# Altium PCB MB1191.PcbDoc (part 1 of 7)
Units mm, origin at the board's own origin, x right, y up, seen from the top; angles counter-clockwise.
Board outline 130 x 80 mm, 8 copper layers (Top, F2, F3, F4, F5, F6, F7, Bottom), stack 1.115 mm thick; 358 components, 347 nets, 1452 pads, 1074 vias.
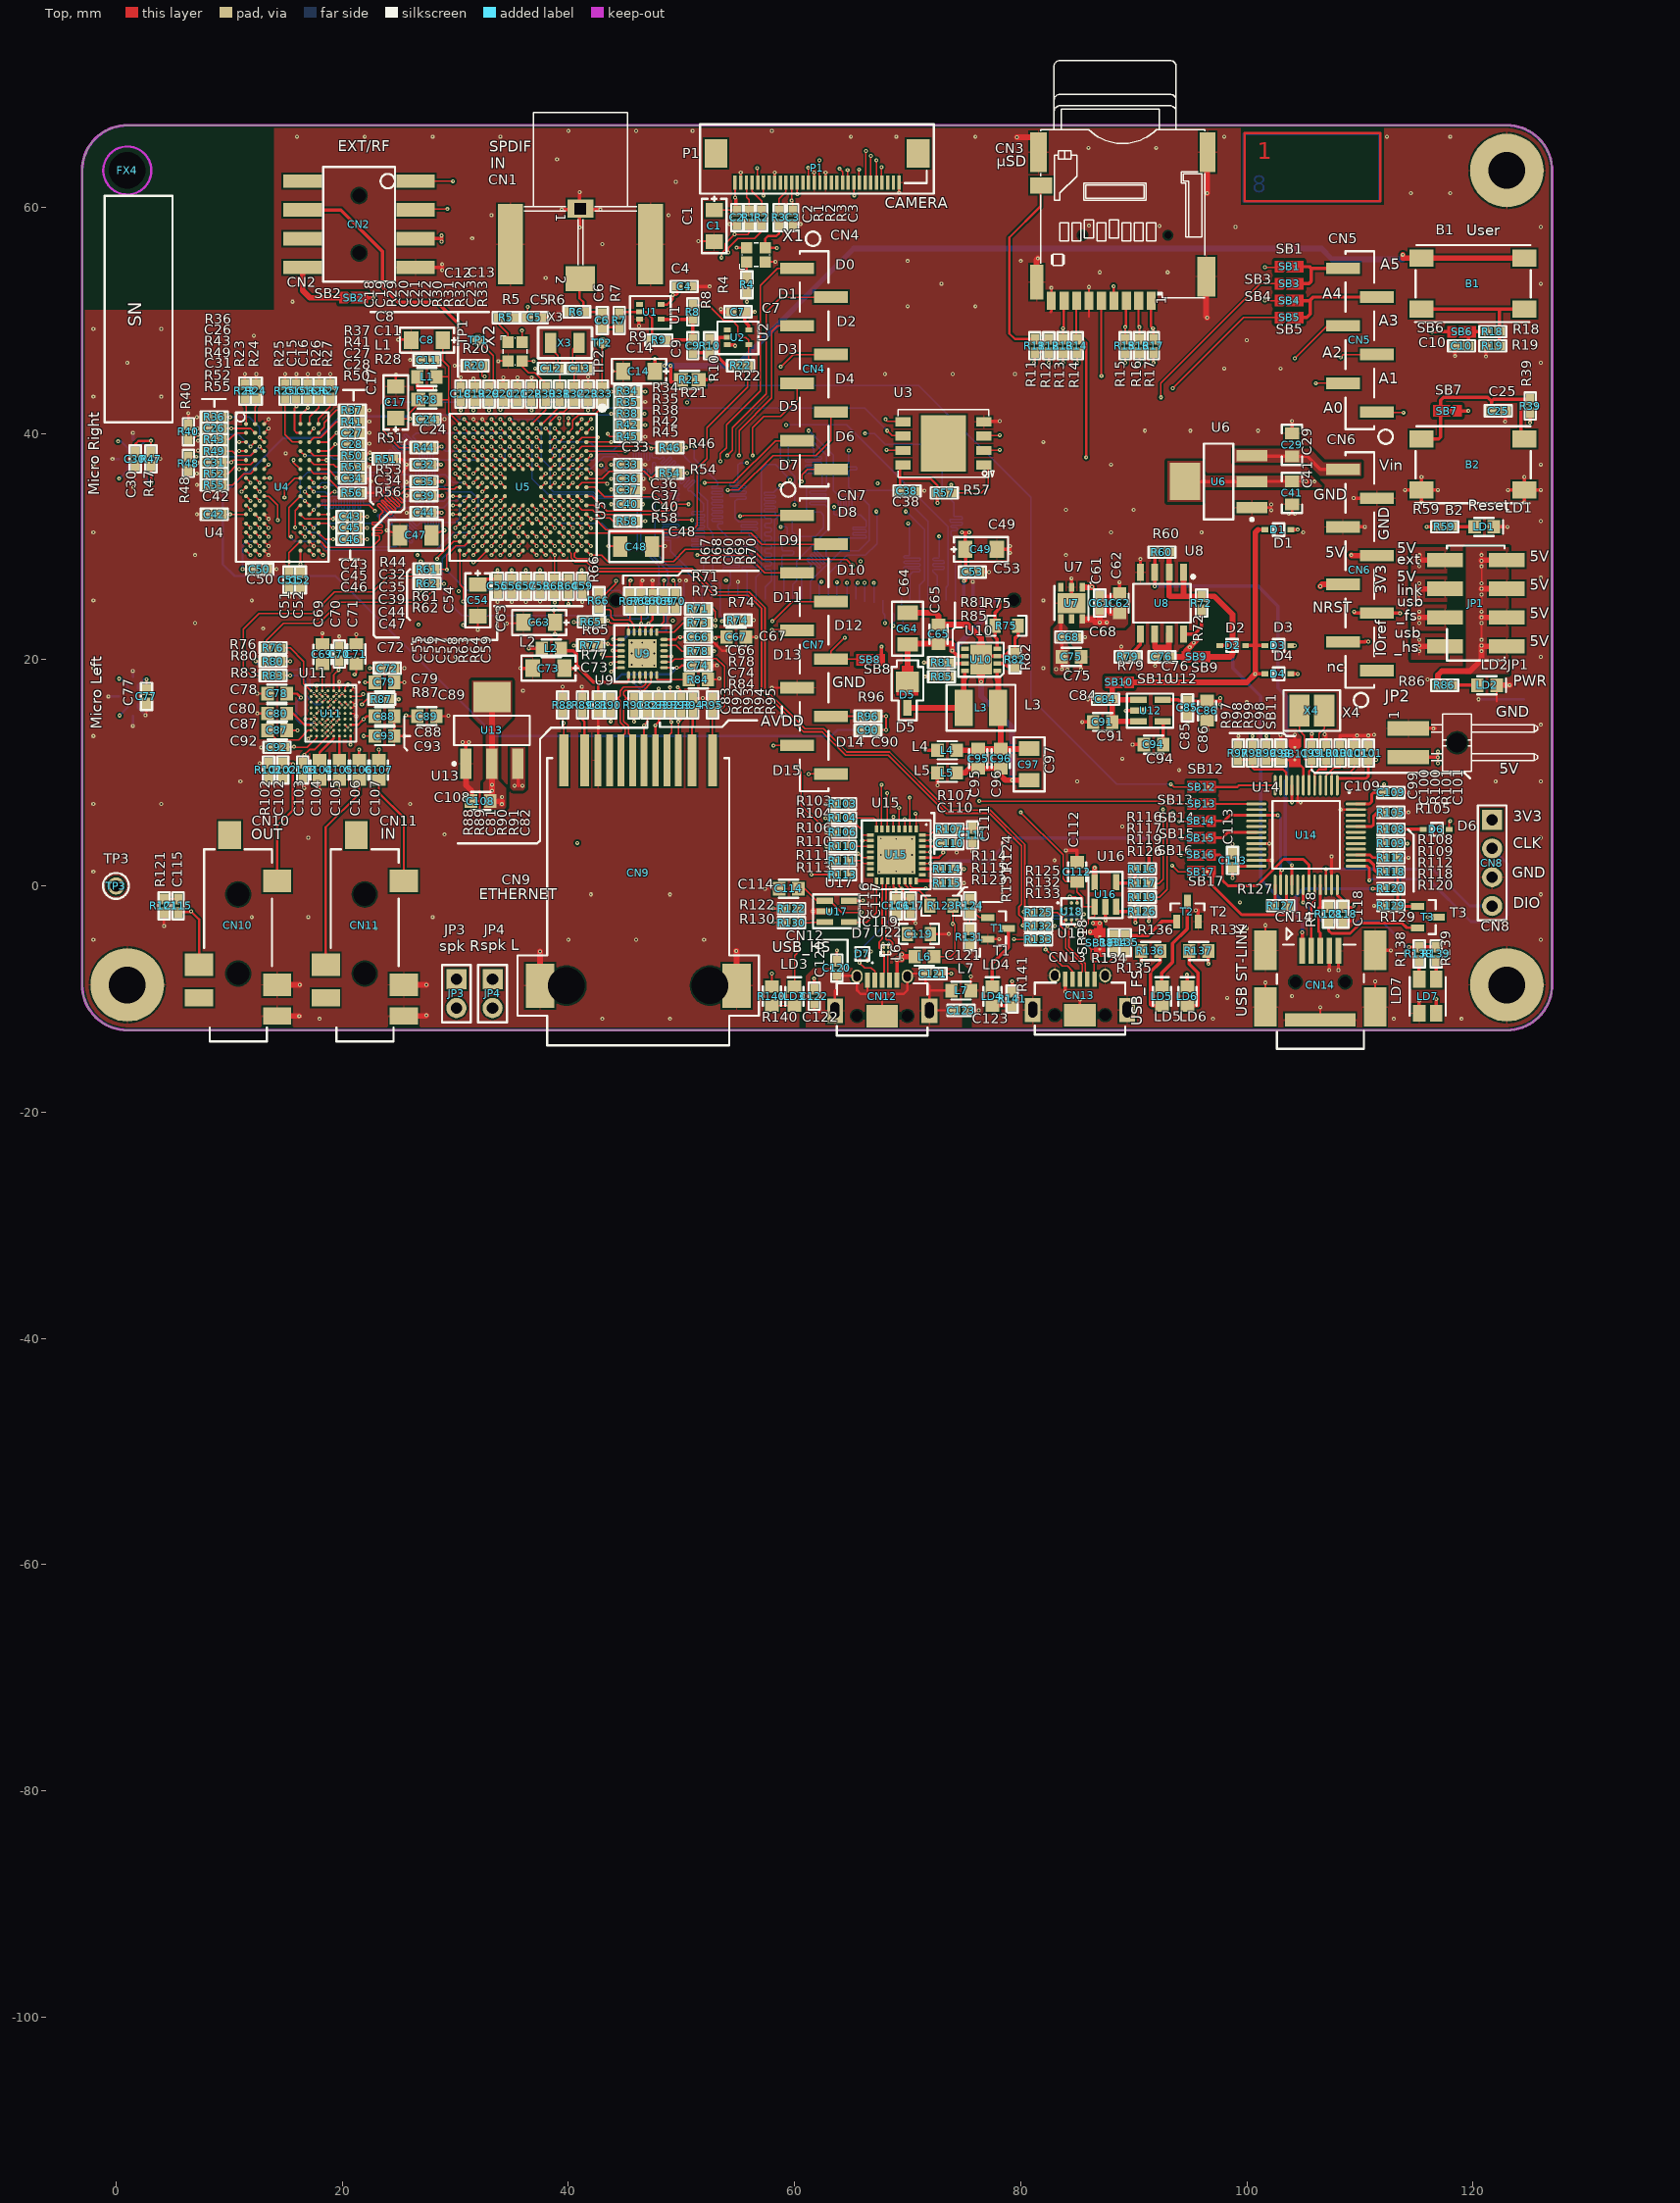
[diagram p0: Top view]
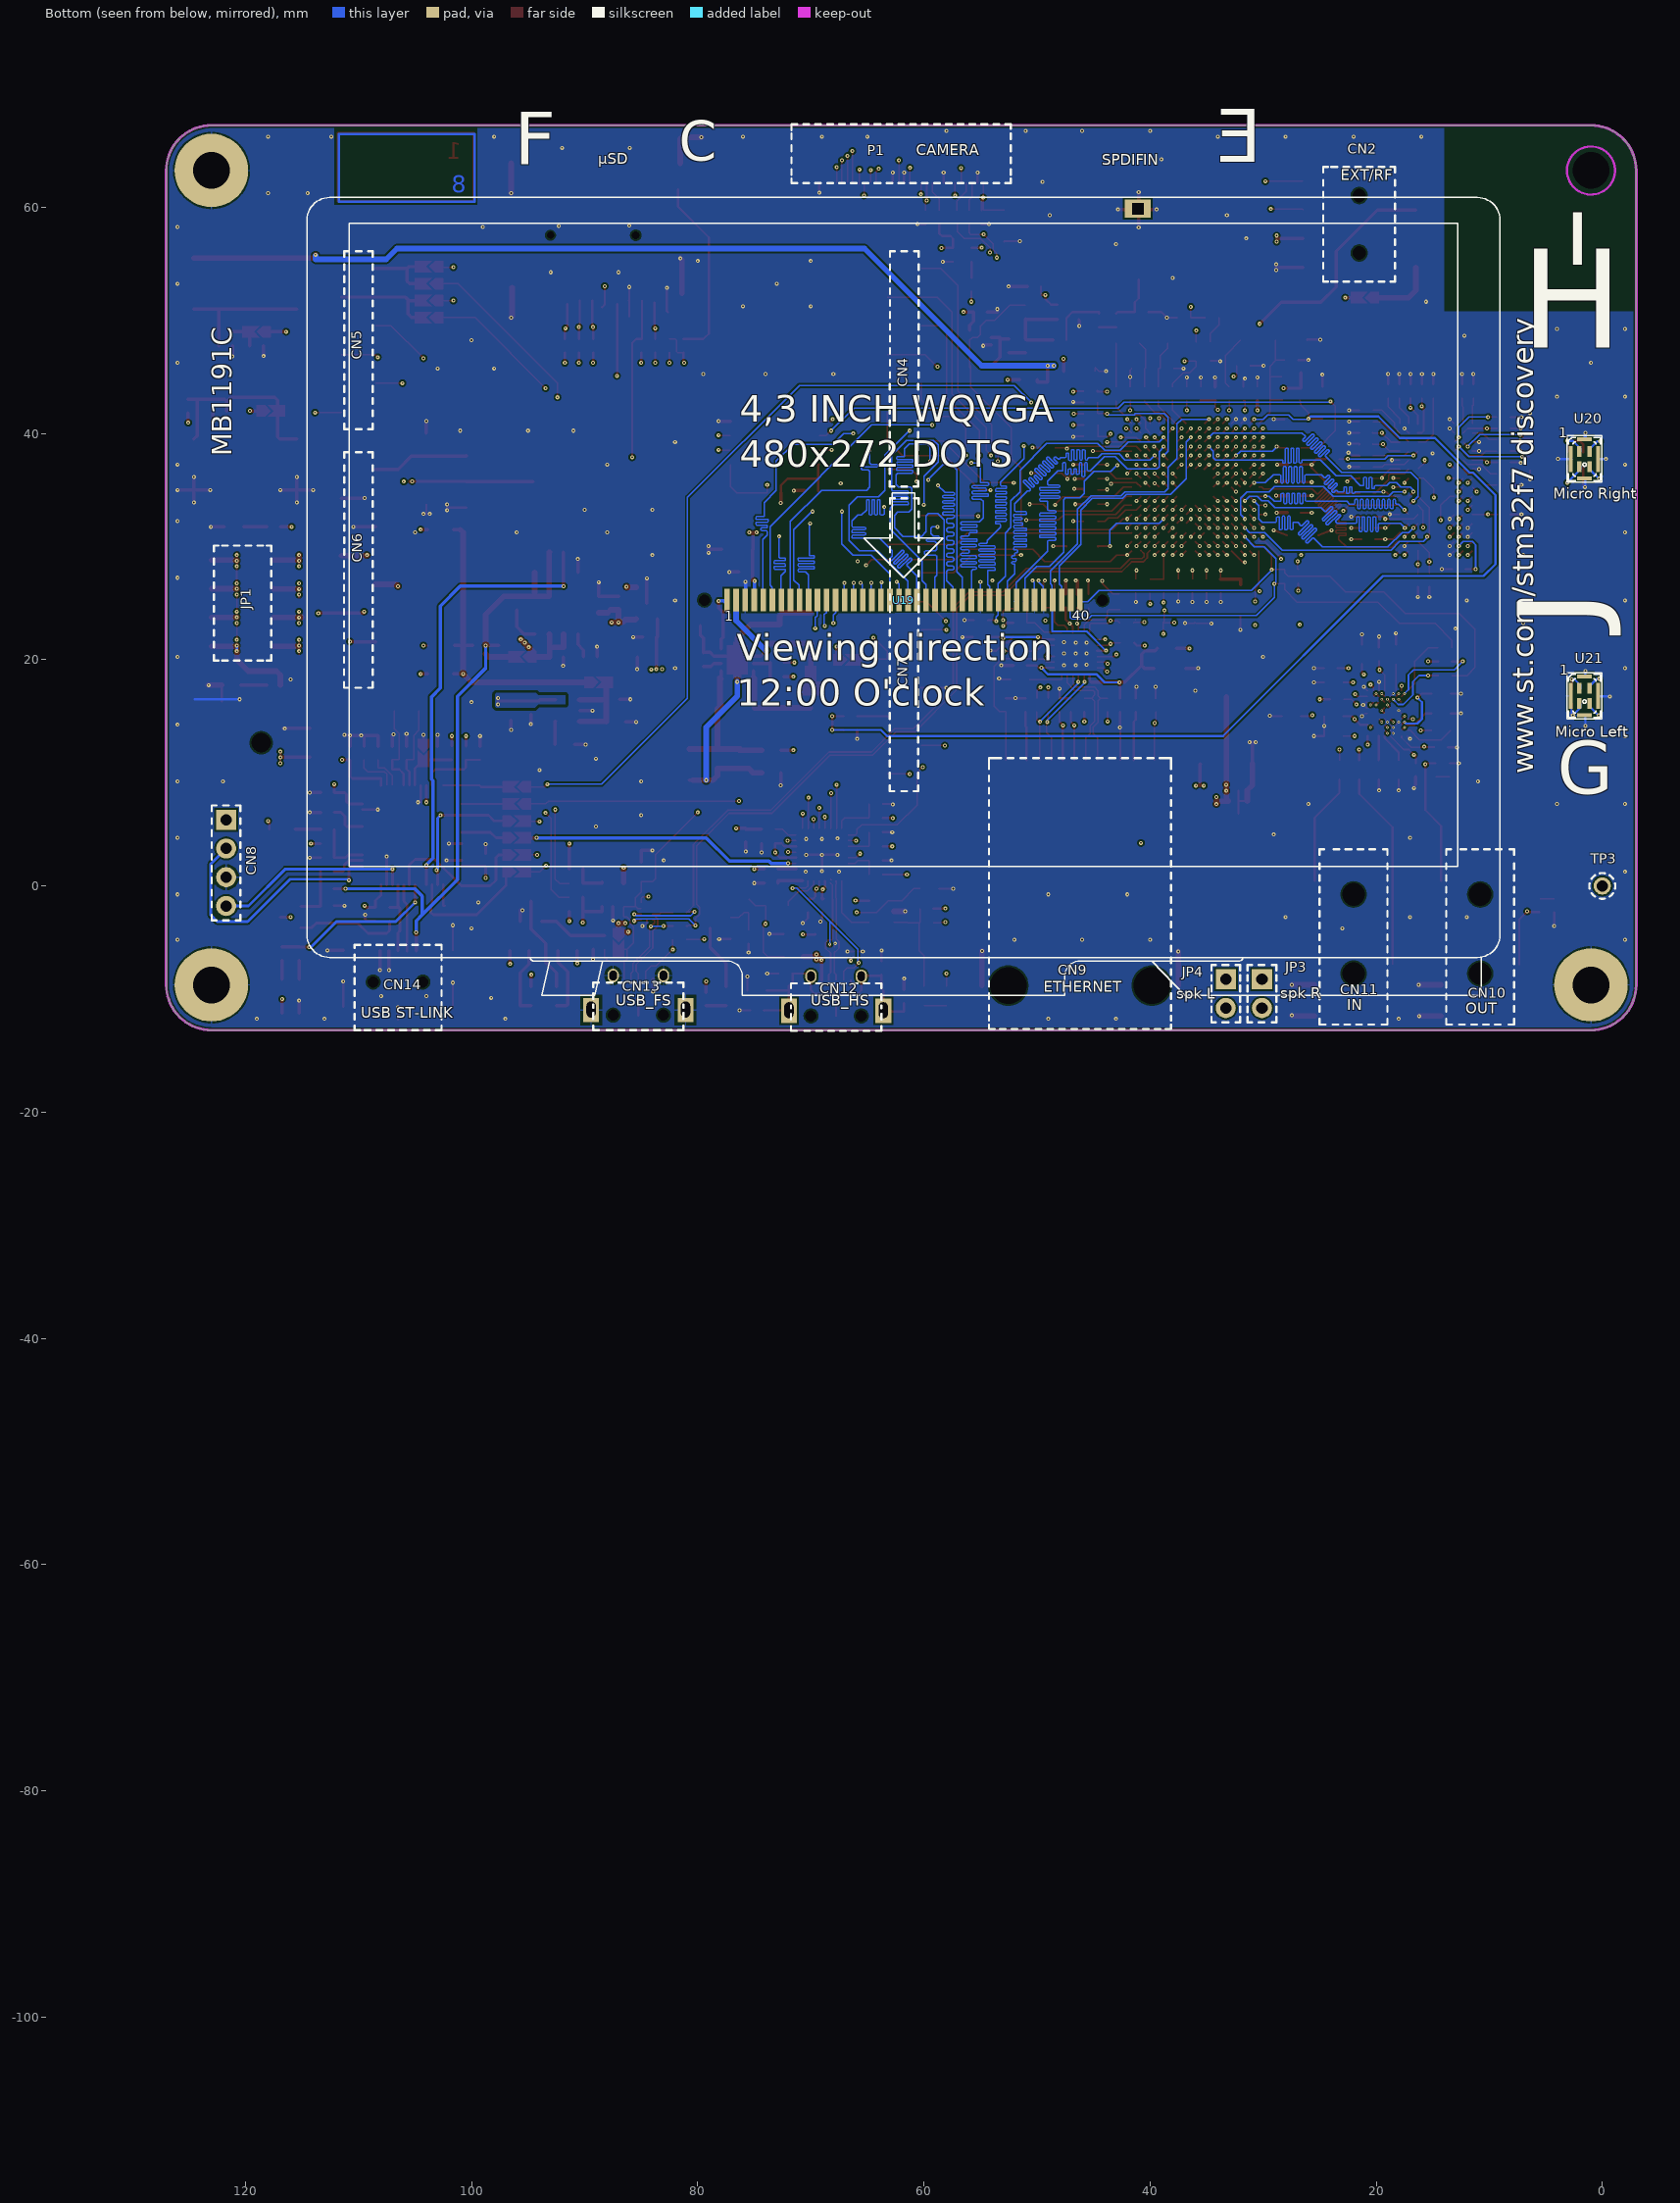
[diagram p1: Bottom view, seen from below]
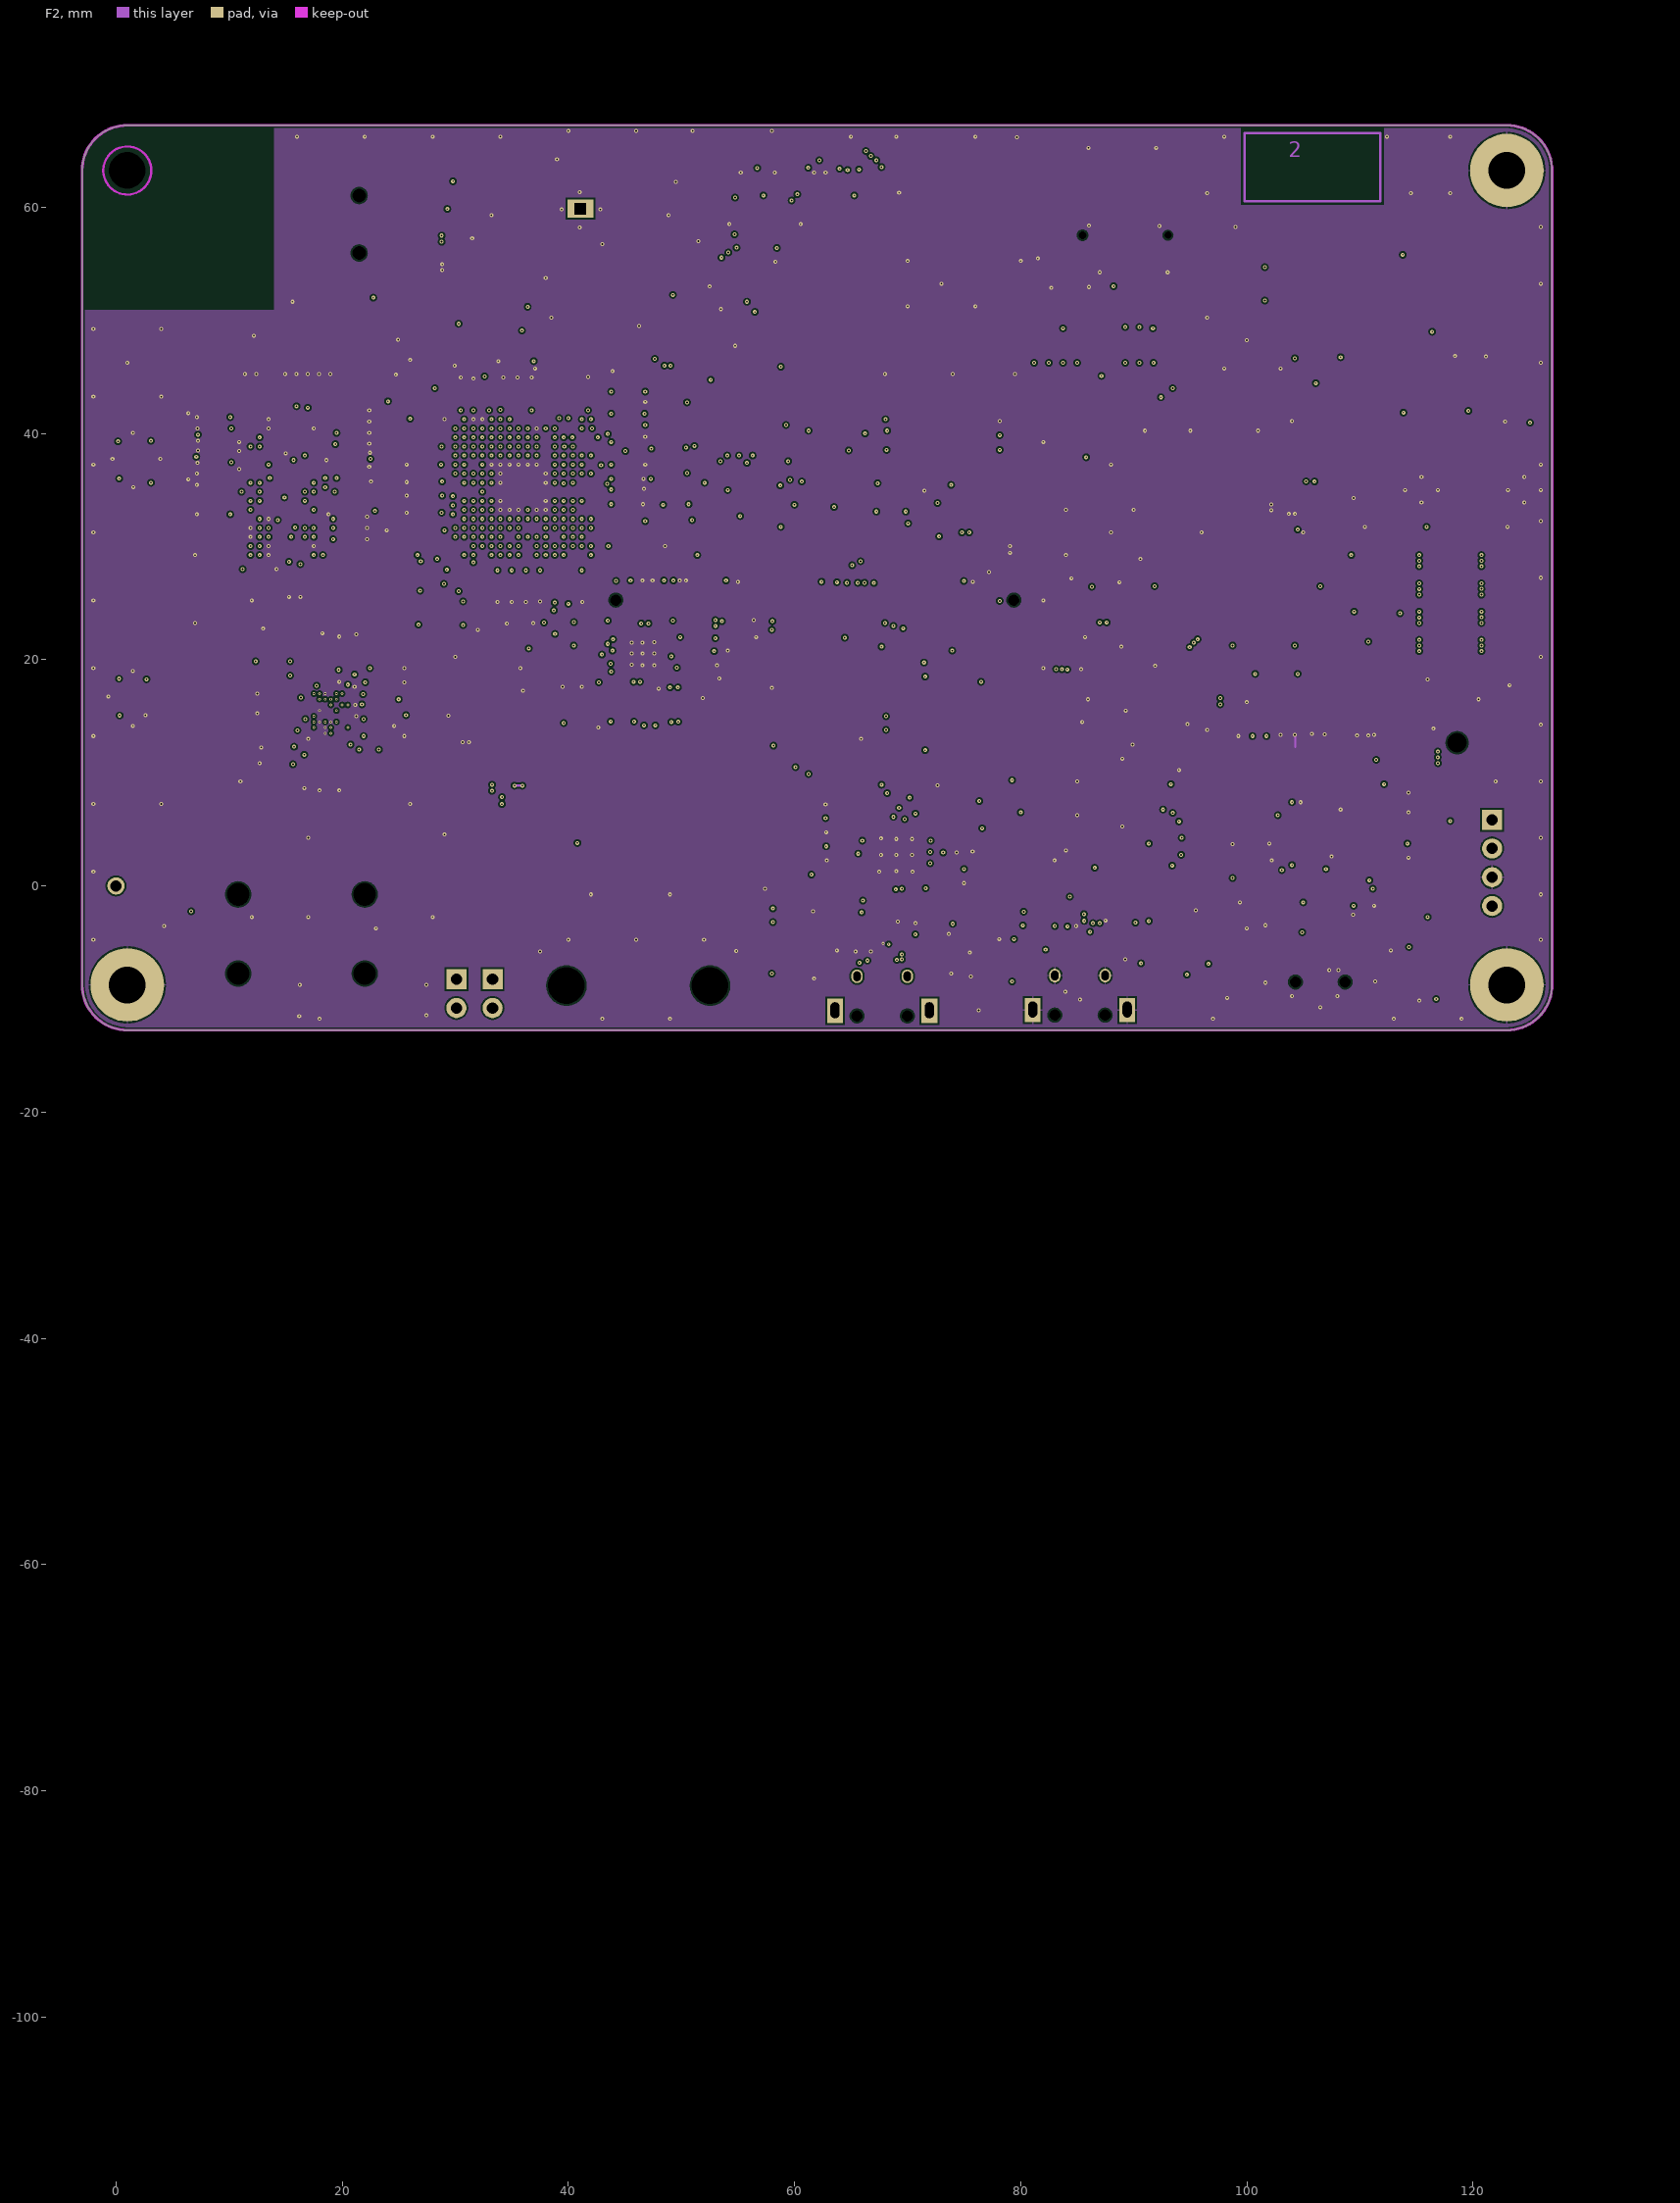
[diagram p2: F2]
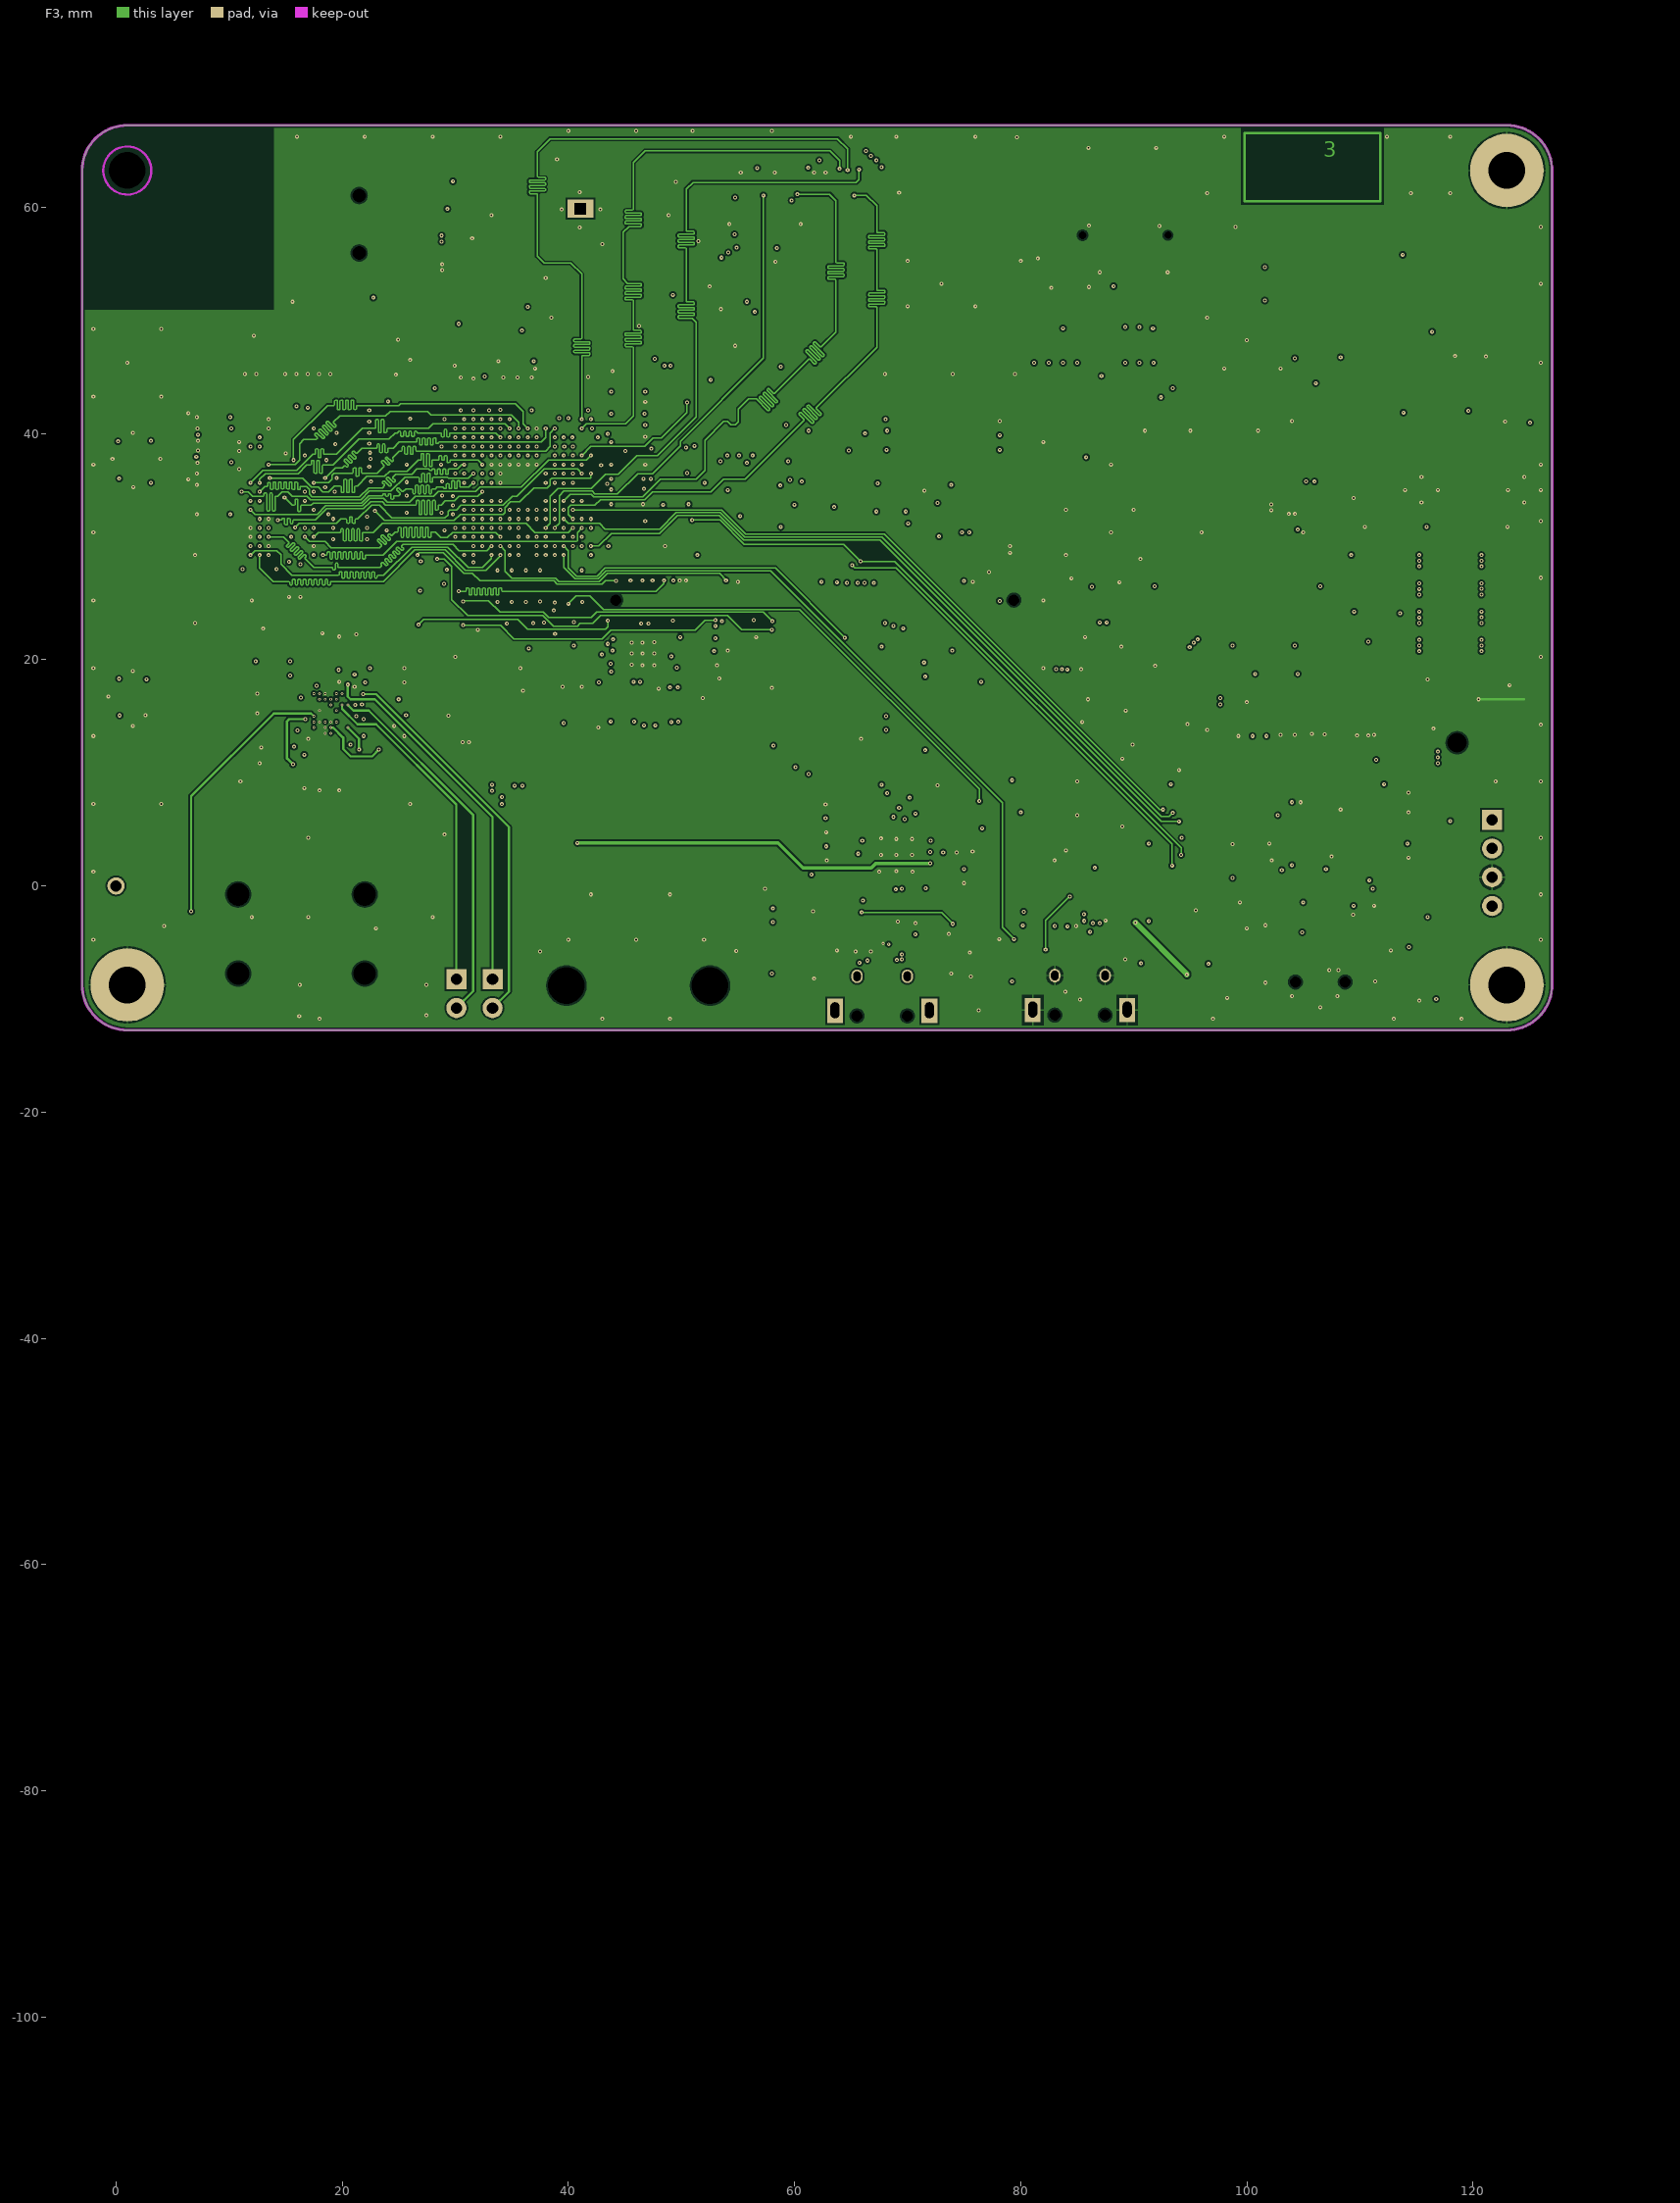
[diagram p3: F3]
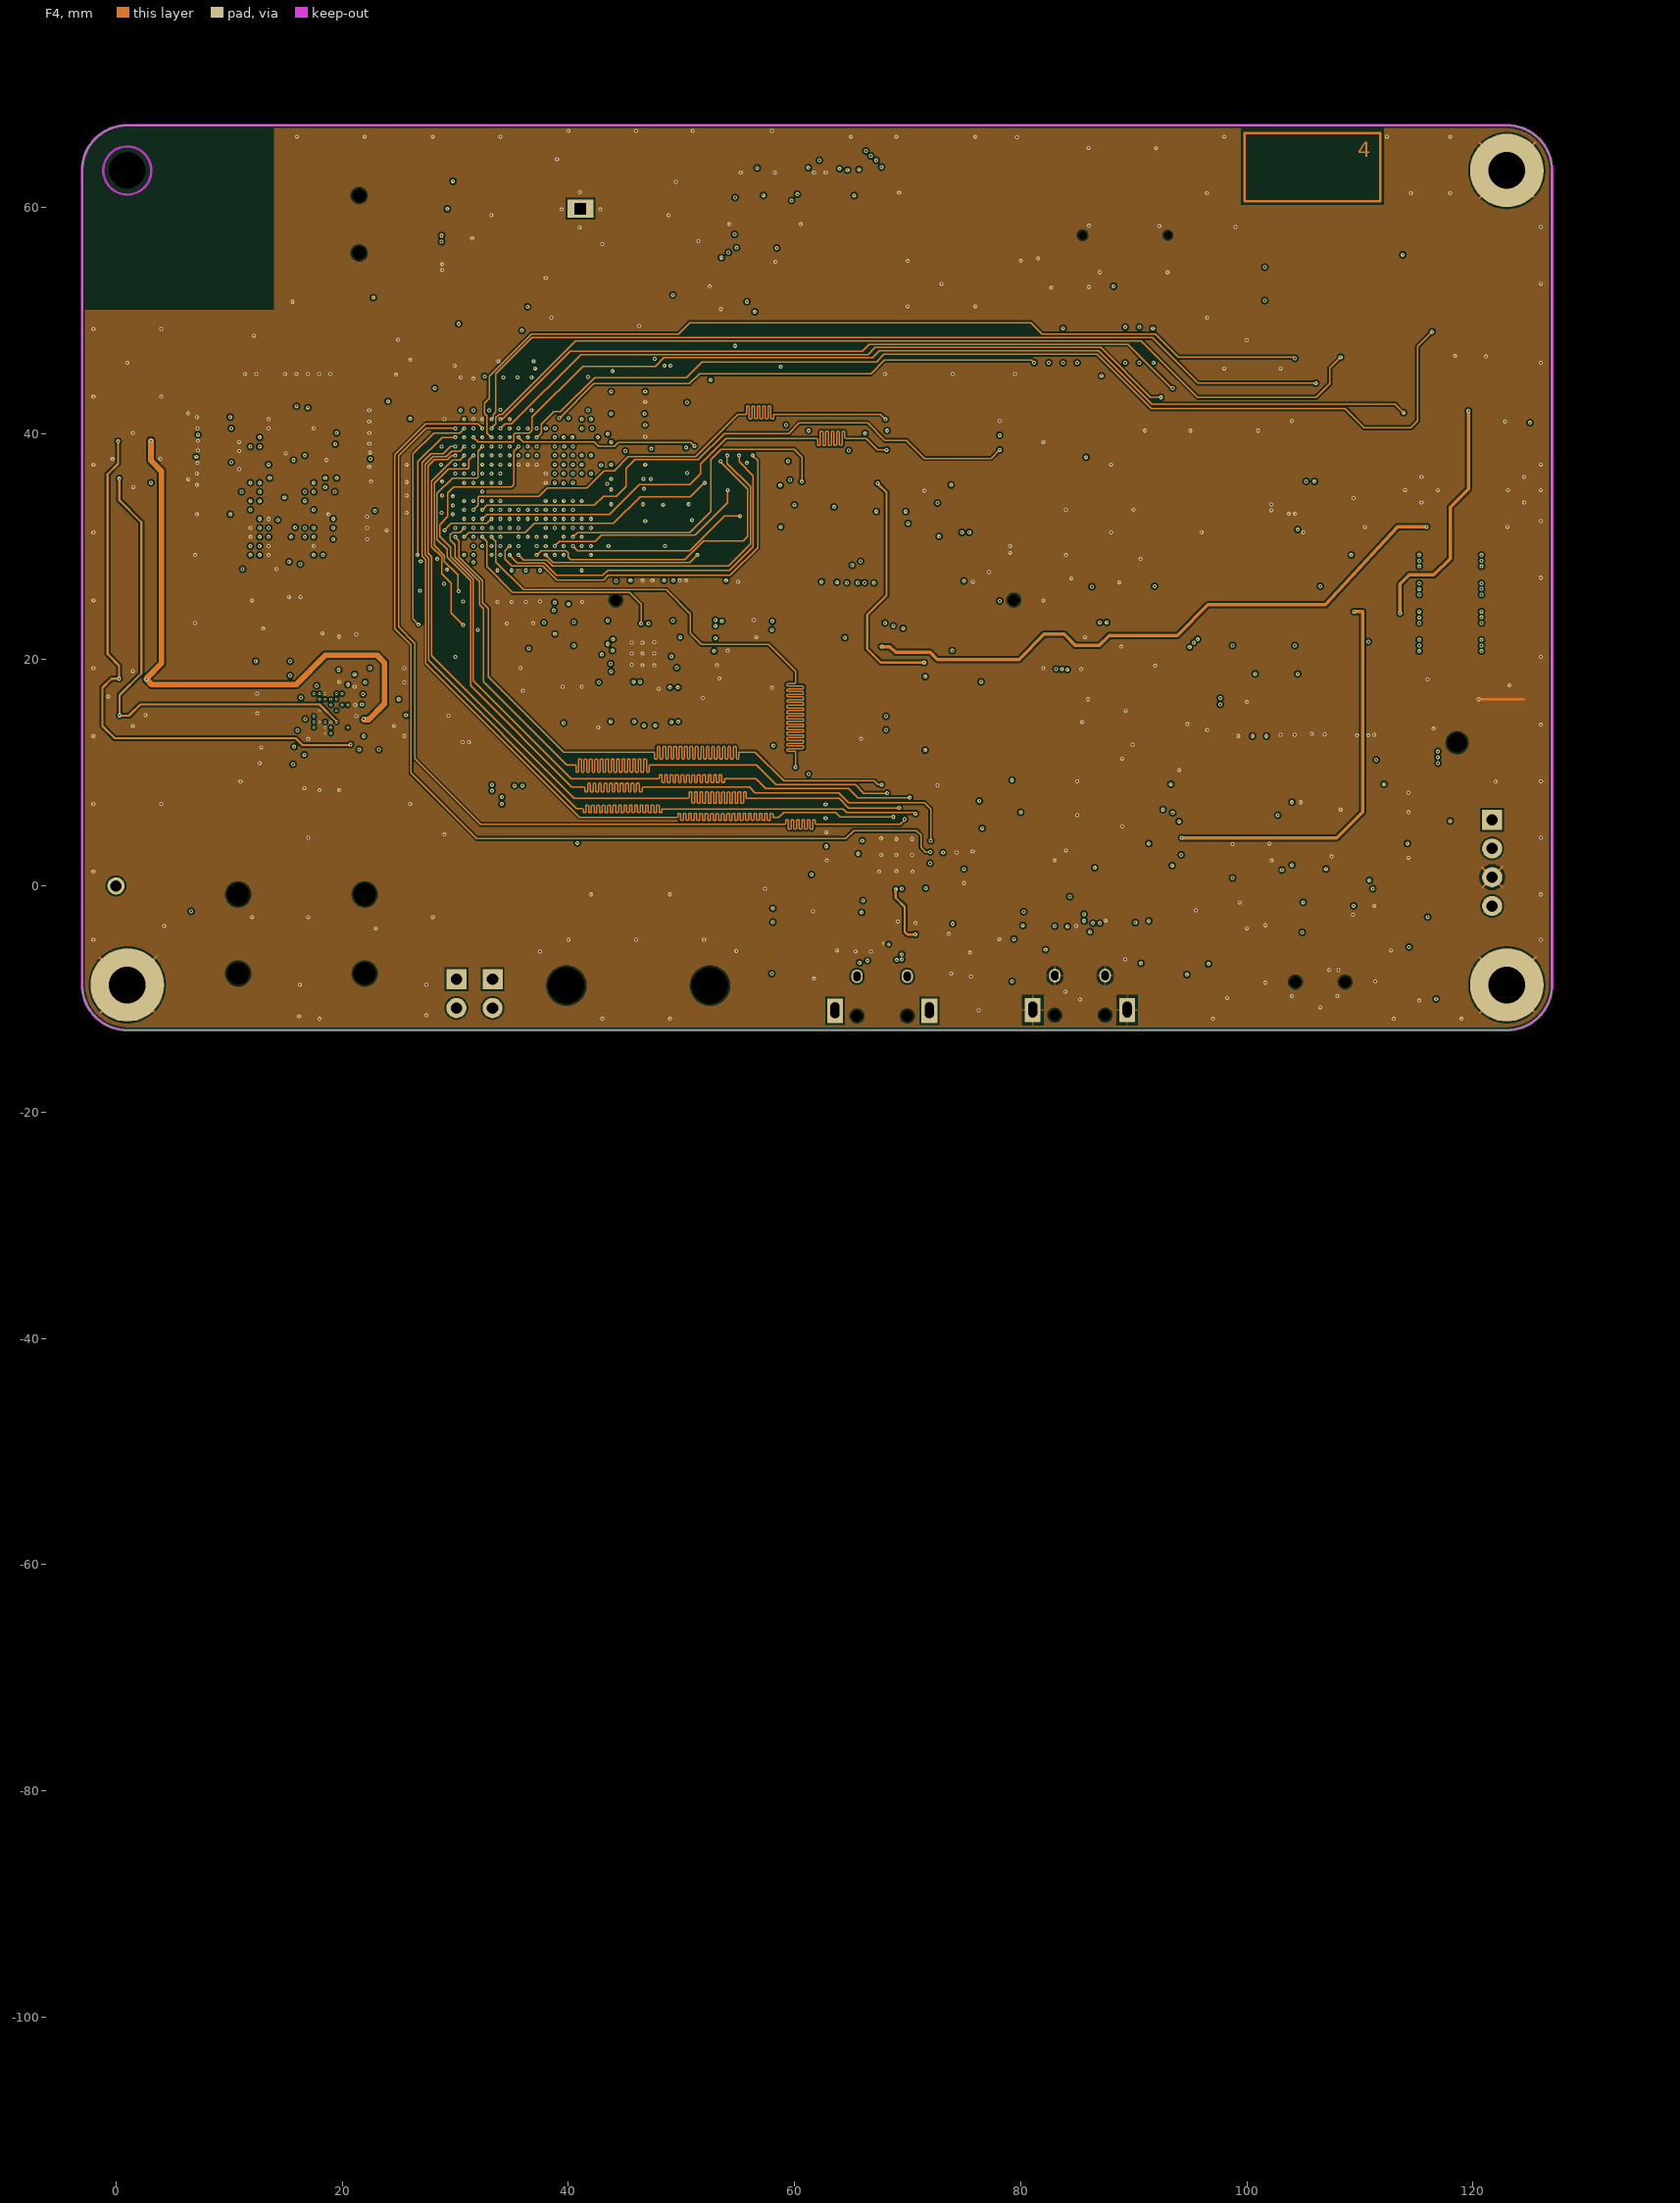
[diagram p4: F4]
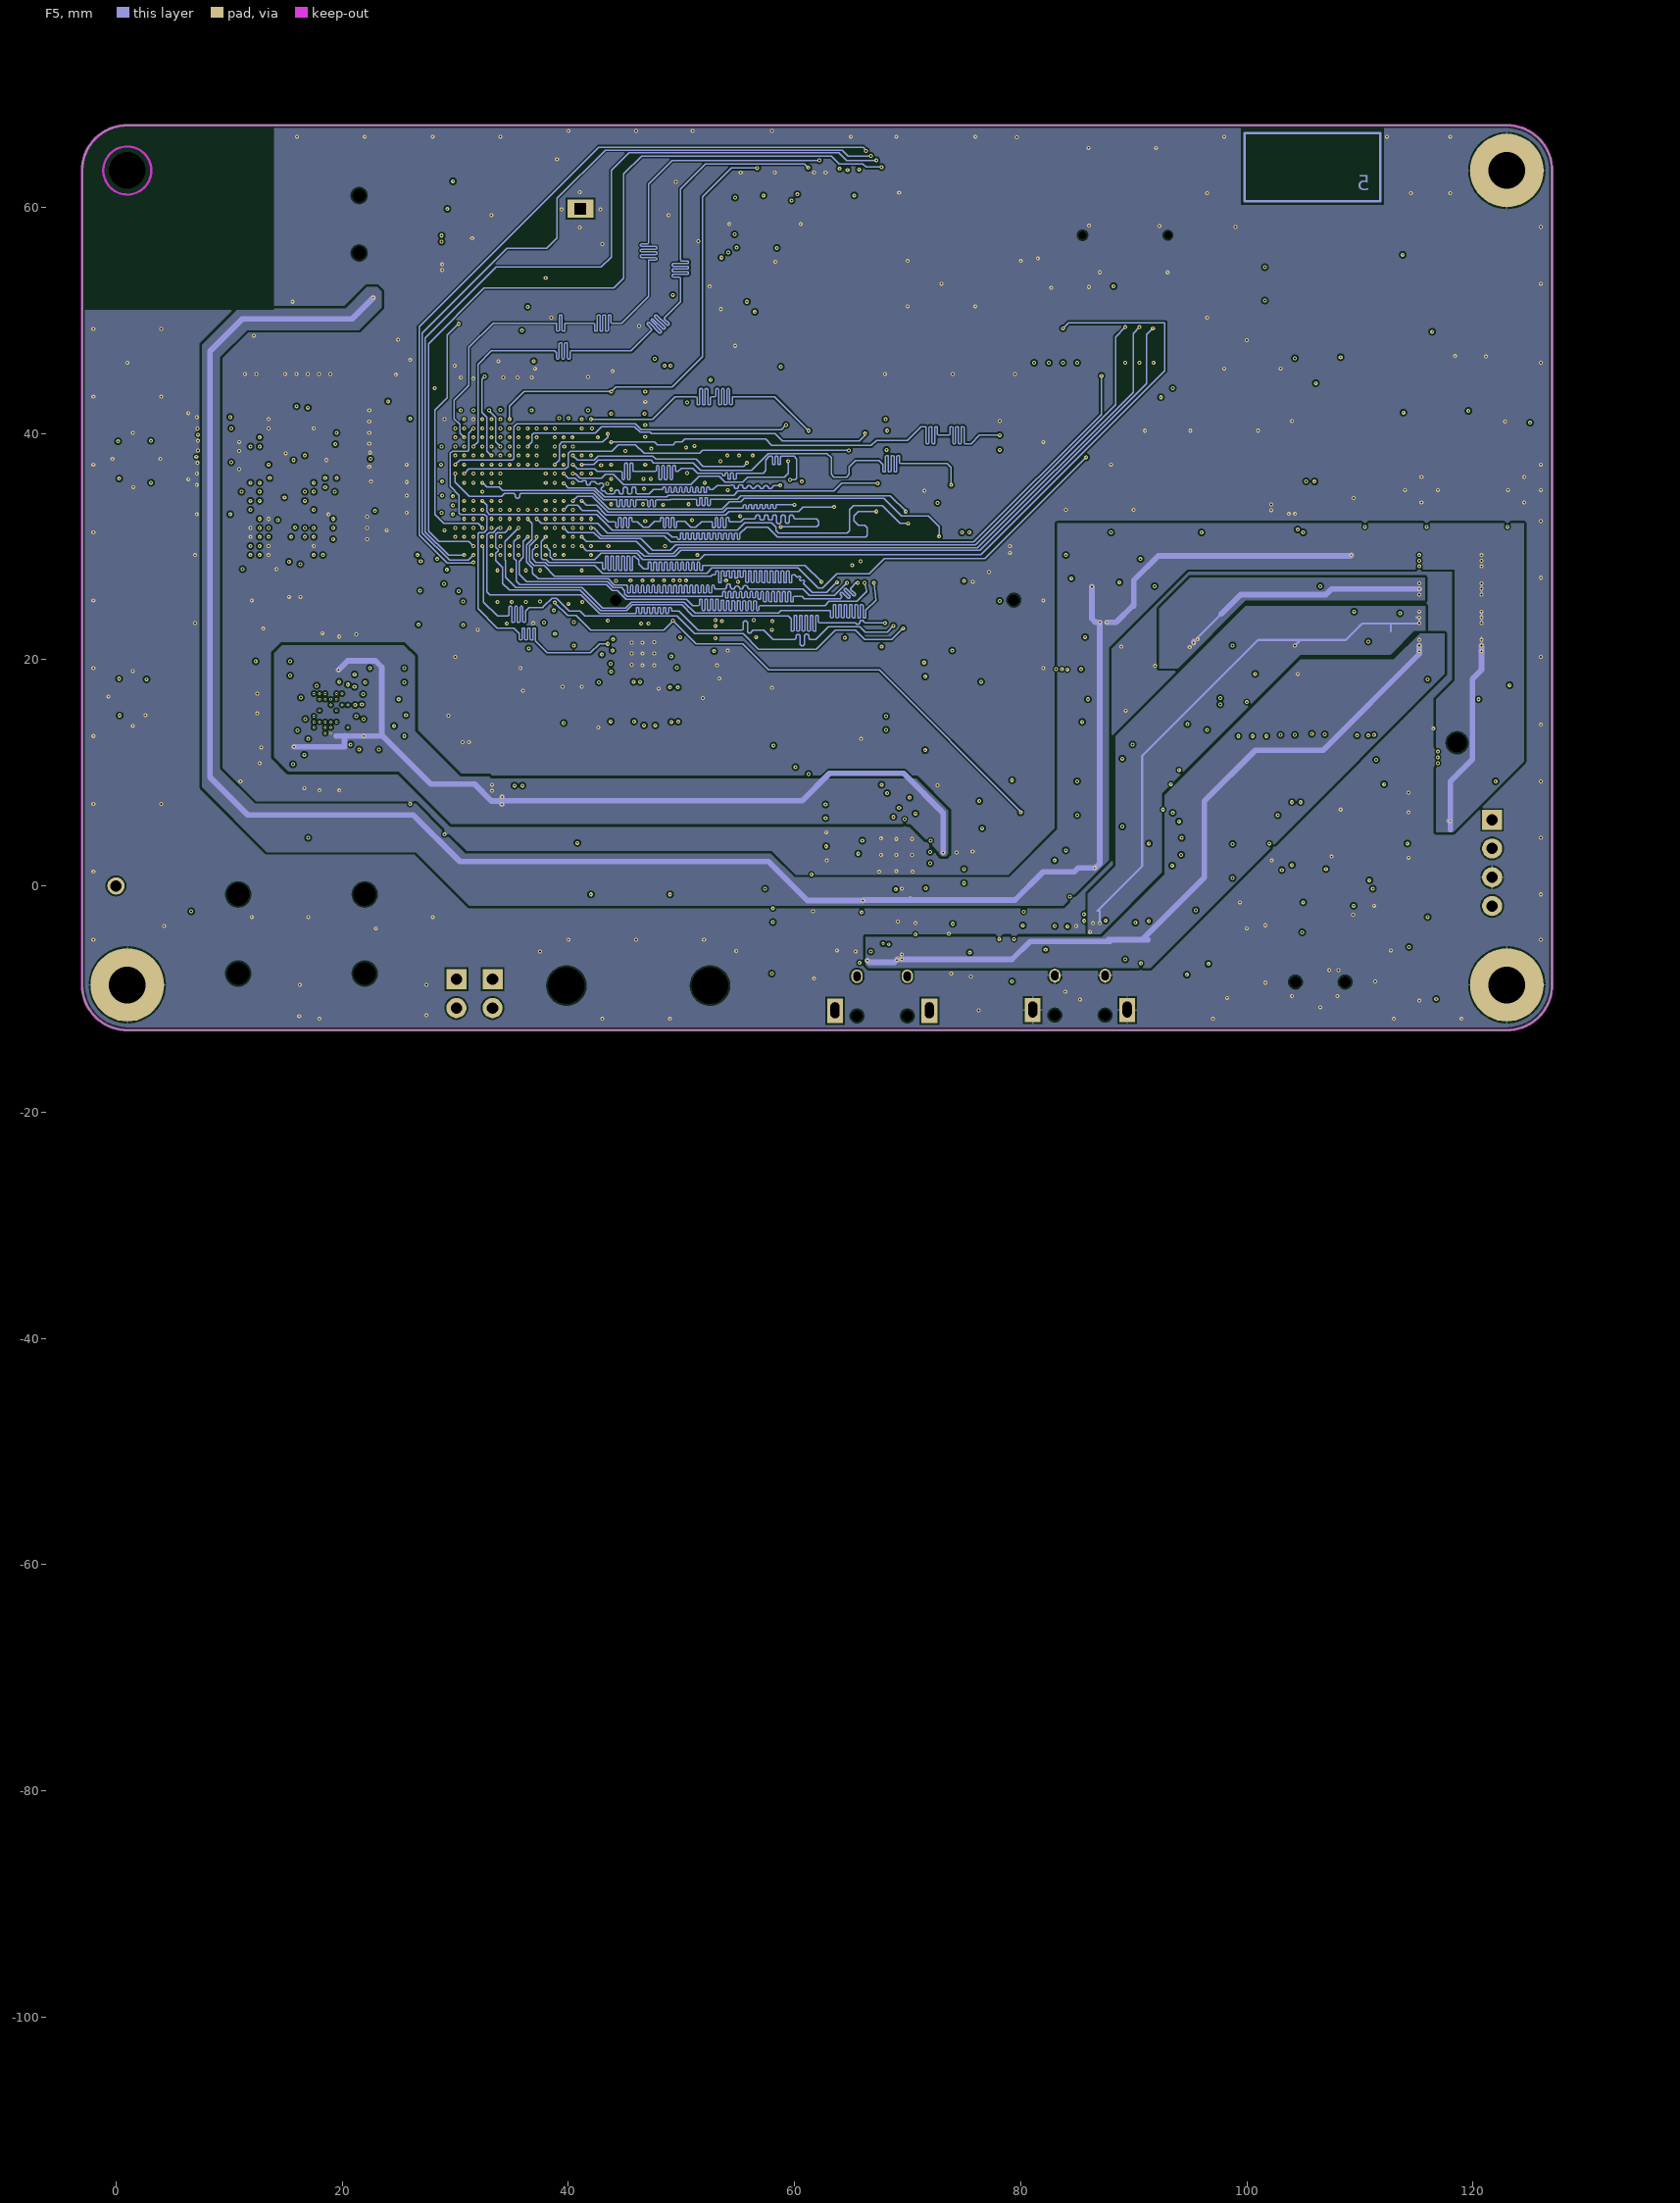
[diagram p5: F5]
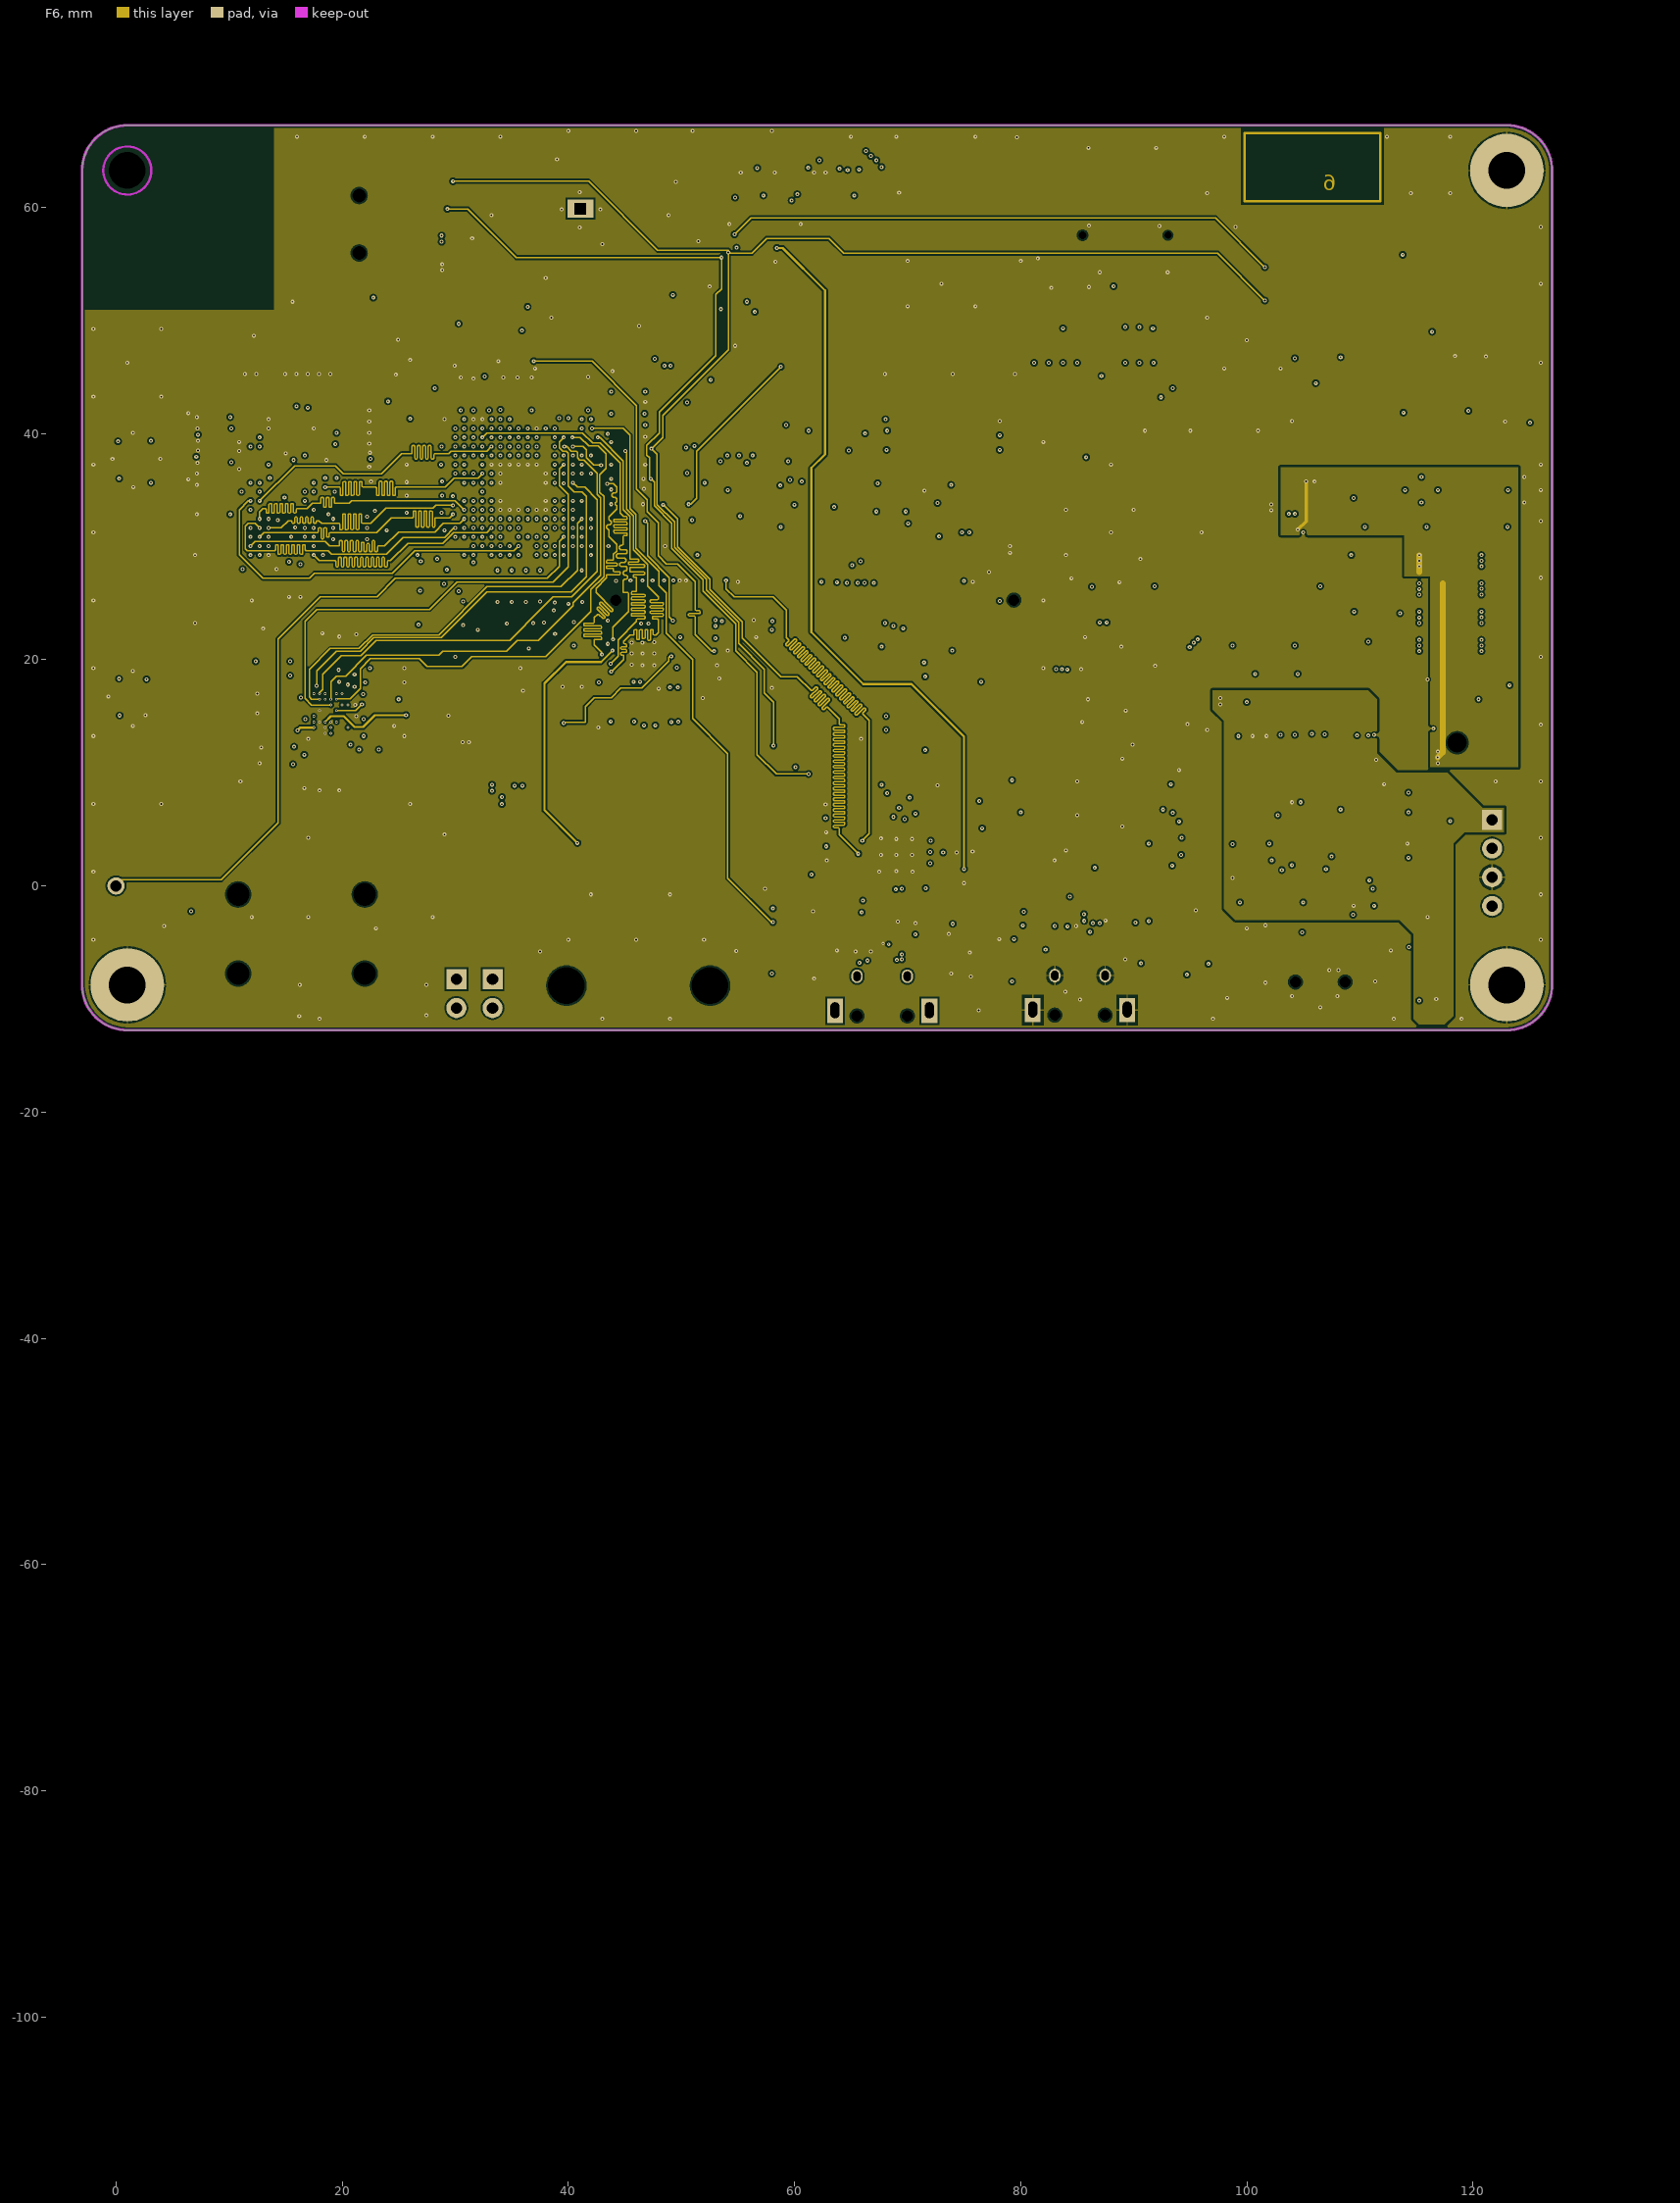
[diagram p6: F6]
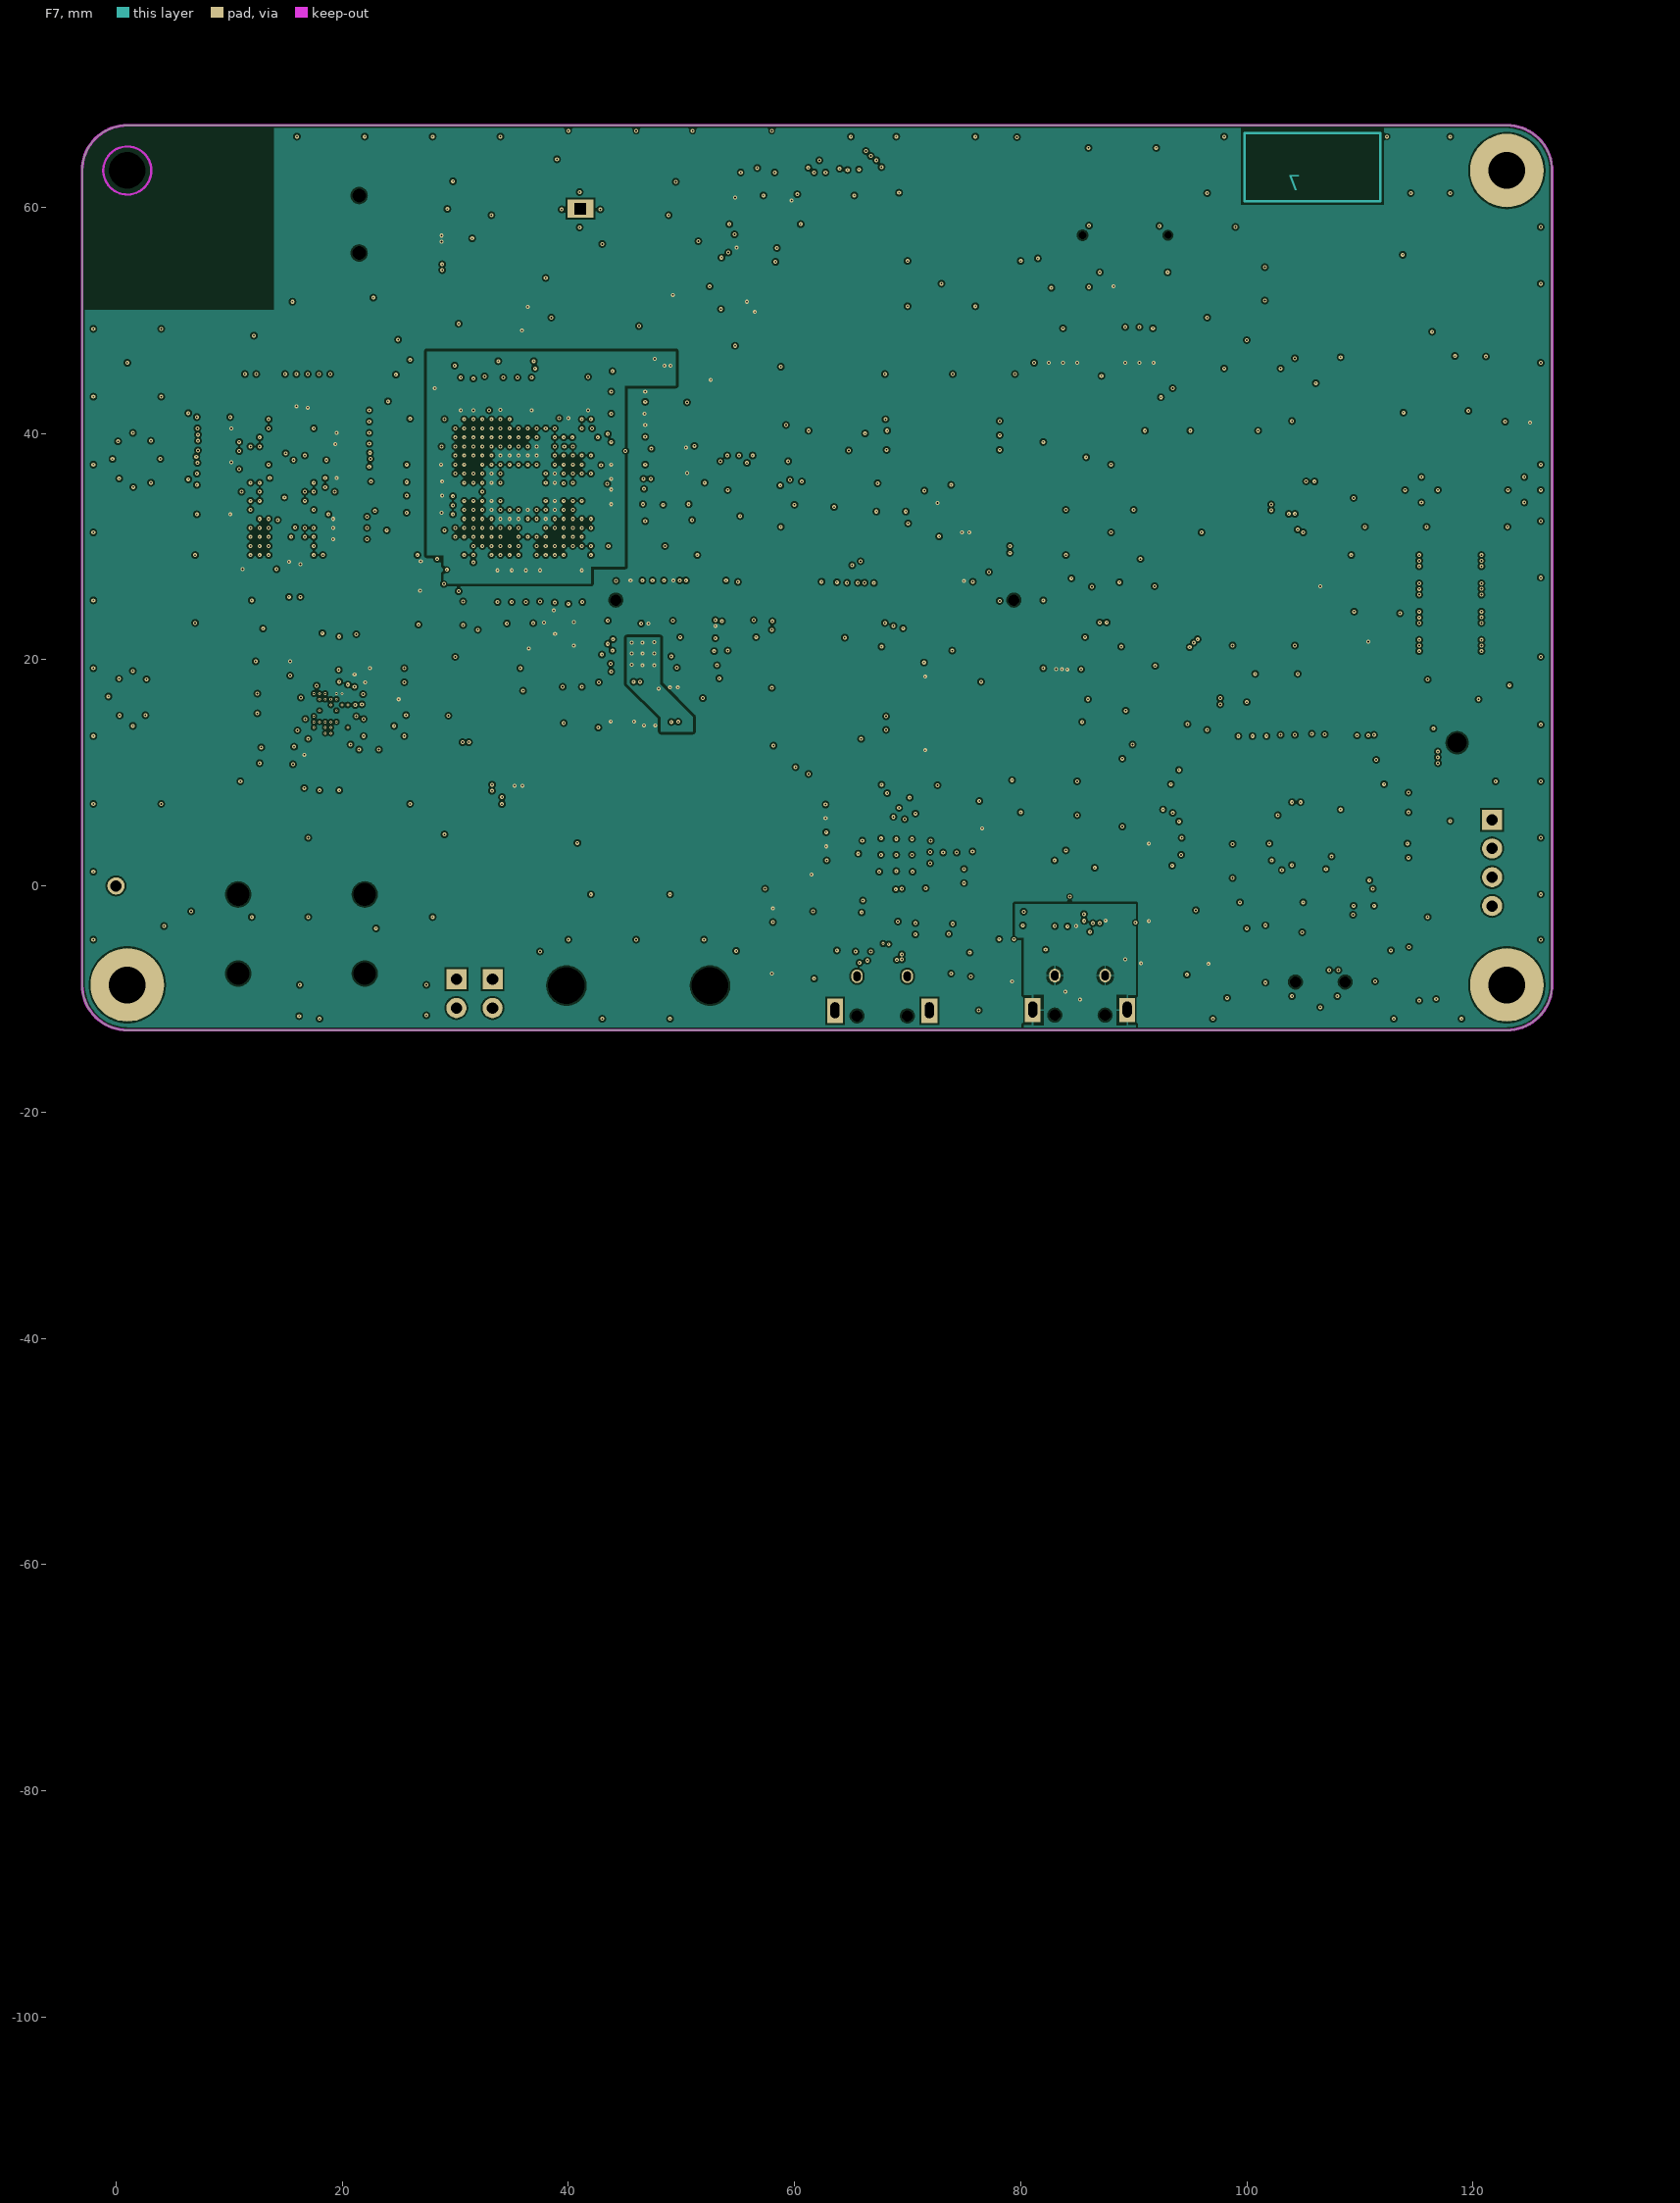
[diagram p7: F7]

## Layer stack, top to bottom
Top Mask: solder mask 0.015, Solder Resist, Dk 3.5
Top: signal copper 0.055
Dielectric 1: prepreg 0.108, Prepreg 2116, Dk 4.2
F2: signal copper 0.033
Dielectric2: core 0.125, Core 125, Dk 4.2
F3: signal copper 0.033
Dielectric3: prepreg 0.108, Prepreg 2116, Dk 4.2
F4: signal copper 0.033
Dielectric4: core 0.125, Core 125, Dk 4.2
F5: signal copper 0.033
Dielectric5: prepreg 0.108, Prepreg 2116, Dk 4.2
F6: signal copper 0.033
Dielectric6: core 0.125, Core 125, Dk 4.2
F7: signal copper 0.033
Dielectric7: prepreg 0.108, Prepreg 2116, Dk 4.2
Bottom: signal copper 0.055
Bottom Solder: solder mask 0.015, Solder Resist, Dk 3.5

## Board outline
-3,-8.75 ccw(c1,-8.75) 1,-12.75 123,-12.75 ccw(c123,-8.75) 127,-8.75 127,63.25 ccw(c123,63.25) 123,67.25 1,67.25 ccw(c1,63.25) -3,63.25

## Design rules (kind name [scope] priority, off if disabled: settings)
Clearance Clearance_CN1-1 [IsPad and (PadViaLibraryTemplate = 'r260_200hn100_160z0x0') vs InPolygon] p1: gap=0.15 ignorepadtopadclearanceinfootprint=FALSE
Clearance "Clearance_Polygon To Polygone" [InPolygon vs InPolygon] p2: gap=0.25 ignorepadtopadclearanceinfootprint=FALSE
Clearance Clearance_JP2_SMD [HasFootprint('JP2_SMD') vs InPolygon] p3: gap=0.25 ignorepadtopadclearanceinfootprint=FALSE
Clearance Clearance_TNM [(ObjectKind = 'Pad') And ((AsMM(HoleDiameter) = 2)) vs Inpolygon] p4: gap=0.15 ignorepadtopadclearanceinfootprint=FALSE
Clearance "Clearance_isvia to BGA" [WithinRoom('RoomDefinition_iso100µm') vs isvia] p5: gap=0.1 ignorepadtopadclearanceinfootprint=FALSE
Clearance "Clearance_Polygon To All" [InPolygon] p6: gap=0.15 ignorepadtopadclearanceinfootprint=FALSE
Clearance CopperToBoard [InPolygon vs (IsTrack Or IsArc) And OnLayer('Keep-out Layer')] p7: gap=0.5 ignorepadtopadclearanceinfootprint=FALSE
Clearance ViaToCopper [IsVia vs InPolygon] p8: gap=0.15 ignorepadtopadclearanceinfootprint=FALSE
Clearance ViaToVia [IsVia vs IsVia] p9: gap=0.15 ignorepadtopadclearanceinfootprint=FALSE
Clearance PadToCopper [IsPad vs InPolygon] p10: gap=0.15 ignorepadtopadclearanceinfootprint=FALSE
Clearance PadToVia [IsPad vs IsVia] p11: gap=0.12 ignorepadtopadclearanceinfootprint=FALSE
Clearance PadToPad [IsPad vs IsPad] p12: gap=0.125 ignorepadtopadclearanceinfootprint=FALSE
Clearance RouteToPad [IsTrack Or IsArc vs IsPad] p13: gap=0.12 ignorepadtopadclearanceinfootprint=FALSE
Clearance RouteToRoute [IsTrack or IsArc vs IsTrack or IsArc] p14: gap=0.12 ignorepadtopadclearanceinfootprint=FALSE
Clearance [All] p15: gap=0.12 ignorepadtopadclearanceinfootprint=FALSE
ComponentClearance [All] p1: gap=0.1 collisioncheckmode=3 verticalgap=0.254 showdistances=FALSE
DiffPairsRouting DiffPairsRouting_USB_FS1 [InDifferentialPair('USB_FS1')] p1: maxlimit=0.13 minlimit=0.13 mostfreqgap=0.13 toplayer_minwidth=0.15 toplayer_maxwidth=0.15 toplayer_prefwidth=0.15 midlayer1_minwidth=0.15 midlayer1_maxwidth=0.15 midlayer1_prefwidth=0.15 midlayer2_minwidth=0.15 midlayer2_maxwidth=0.15 midlayer2_prefwidth=0.15 midlayer3_minwidth=0.15 midlayer3_maxwidth=0.15 midlayer3_prefwidth=0.15 midlayer4_minwidth=0.15 midlayer4_maxwidth=0.15 midlayer4_prefwidth=0.15 midlayer5_minwidth=0.15 midlayer5_maxwidth=0.15 midlayer5_prefwidth=0.15 midlayer6_minwidth=0.15 midlayer6_maxwidth=0.15 midlayer6_prefwidth=0.15 bottomlayer_minwidth=0.15 bottomlayer_maxwidth=0.15 bottomlayer_prefwidth=0.15 maxuncoupledlength=12.7
DiffPairsRouting DiffPairsRouting_USB_HS [InDifferentialPair('USB_HS')] p2: maxlimit=0.17 minlimit=0.17 mostfreqgap=0.17 toplayer_minwidth=0.15 toplayer_maxwidth=0.15 toplayer_prefwidth=0.15 midlayer1_minwidth=0.15 midlayer1_maxwidth=0.15 midlayer1_prefwidth=0.15 midlayer2_minwidth=0.15 midlayer2_maxwidth=0.15 midlayer2_prefwidth=0.15 midlayer3_minwidth=0.15 midlayer3_maxwidth=0.15 midlayer3_prefwidth=0.15 midlayer4_minwidth=0.15 midlayer4_maxwidth=0.15 midlayer4_prefwidth=0.15 midlayer5_minwidth=0.15 midlayer5_maxwidth=0.15 midlayer5_prefwidth=0.15 midlayer6_minwidth=0.15 midlayer6_maxwidth=0.15 midlayer6_prefwidth=0.15 bottomlayer_minwidth=0.15 bottomlayer_maxwidth=0.15 bottomlayer_prefwidth=0.15 maxuncoupledlength=12.7
DiffPairsRouting DiffPairsRouting_TD [InDifferentialPair('TD')] p3: maxlimit=0.175 minlimit=0.175 mostfreqgap=0.175 toplayer_minwidth=0.125 toplayer_maxwidth=0.125 toplayer_prefwidth=0.125 midlayer1_minwidth=0.125 midlayer1_maxwidth=0.125 midlayer1_prefwidth=0.125 midlayer2_minwidth=0.125 midlayer2_maxwidth=0.125 midlayer2_prefwidth=0.125 midlayer3_minwidth=0.125 midlayer3_maxwidth=0.125 midlayer3_prefwidth=0.125 midlayer4_minwidth=0.125 midlayer4_maxwidth=0.125 midlayer4_prefwidth=0.125 midlayer5_minwidth=0.125 midlayer5_maxwidth=0.125 midlayer5_prefwidth=0.125 midlayer6_minwidth=0.125 midlayer6_maxwidth=0.125 midlayer6_prefwidth=0.125 bottomlayer_minwidth=0.125 bottomlayer_maxwidth=0.125 bottomlayer_prefwidth=0.125 maxuncoupledlength=12.7
DiffPairsRouting DiffPairsRouting_RD [InDifferentialPair('RD')] p4: maxlimit=0.165 minlimit=0.165 mostfreqgap=0.165 toplayer_minwidth=0.125 toplayer_maxwidth=0.125 toplayer_prefwidth=0.125 midlayer1_minwidth=0.125 midlayer1_maxwidth=0.125 midlayer1_prefwidth=0.125 midlayer2_minwidth=0.125 midlayer2_maxwidth=0.125 midlayer2_prefwidth=0.125 midlayer3_minwidth=0.125 midlayer3_maxwidth=0.125 midlayer3_prefwidth=0.125 midlayer4_minwidth=0.125 midlayer4_maxwidth=0.125 midlayer4_prefwidth=0.125 midlayer5_minwidth=0.125 midlayer5_maxwidth=0.125 midlayer5_prefwidth=0.125 midlayer6_minwidth=0.125 midlayer6_maxwidth=0.125 midlayer6_prefwidth=0.125 bottomlayer_minwidth=0.125 bottomlayer_maxwidth=0.125 bottomlayer_prefwidth=0.125 maxuncoupledlength=12.7
HoleSize [All] p1: absolutevalues=TRUE maxlimit=10 minlimit=0.025 maxpercent=80.000 minpercent=20.000
MatchedLengths "Schematic Matched Net Lengths_43" [InNet('USB_HS_P')] p1: tolerance=3.81 checknetsindiffpair=TRUE checkdiffpairvsdiffpair=FALSE checkxsignals=FALSE checkothers=FALSE
MatchedLengths "Schematic Matched Net Lengths_42" [InNet('USB_HS_N')] p2: tolerance=3.81 checknetsindiffpair=TRUE checkdiffpairvsdiffpair=FALSE checkxsignals=FALSE checkothers=FALSE
MatchedLengths "Schematic Matched Net Lengths_41" [InNet('PG15')] p3: tolerance=2.54 checknetsindiffpair=FALSE checkdiffpairvsdiffpair=TRUE checkxsignals=TRUE checkothers=TRUE
MatchedLengths "Schematic Matched Net Lengths_40" [InNet('PA5')] p4: tolerance=2.54 checknetsindiffpair=FALSE checkdiffpairvsdiffpair=TRUE checkxsignals=TRUE checkothers=TRUE
MatchedLengths "Schematic Matched Net Lengths_39" [InNet('PH3')] p5: tolerance=2.54 checknetsindiffpair=FALSE checkdiffpairvsdiffpair=TRUE checkxsignals=TRUE checkothers=TRUE
MatchedLengths "Schematic Matched Net Lengths_38" [InNet('PH5')] p6: tolerance=2.54 checknetsindiffpair=FALSE checkdiffpairvsdiffpair=TRUE checkxsignals=TRUE checkothers=TRUE
MatchedLengths "Schematic Matched Net Lengths_37" [InNet('PD12')] p7: tolerance=2.54 checknetsindiffpair=FALSE checkdiffpairvsdiffpair=TRUE checkxsignals=TRUE checkothers=TRUE
MatchedLengths "Schematic Matched Net Lengths_36" [InNet('PC5')] p8: tolerance=2.54 checknetsindiffpair=FALSE checkdiffpairvsdiffpair=TRUE checkxsignals=TRUE checkothers=TRUE
MatchedLengths "Schematic Matched Net Lengths_35" [InNet('PD11')] p9: tolerance=2.54 checknetsindiffpair=FALSE checkdiffpairvsdiffpair=TRUE checkxsignals=TRUE checkothers=TRUE
MatchedLengths "Schematic Matched Net Lengths_34" [InNet('PC2')] p10: tolerance=2.54 checknetsindiffpair=FALSE checkdiffpairvsdiffpair=TRUE checkxsignals=TRUE checkothers=TRUE
MatchedLengths "Schematic Matched Net Lengths_33" [InNet('PC0')] p11: tolerance=2.54 checknetsindiffpair=FALSE checkdiffpairvsdiffpair=TRUE checkxsignals=TRUE checkothers=TRUE
MatchedLengths "Schematic Matched Net Lengths_32" [InNet('PG9')] p12: tolerance=2.54 checknetsindiffpair=FALSE checkdiffpairvsdiffpair=TRUE checkxsignals=TRUE checkothers=TRUE
MatchedLengths "Schematic Matched Net Lengths_31" [InNet('PC3')] p13: tolerance=2.54 checknetsindiffpair=FALSE checkdiffpairvsdiffpair=TRUE checkxsignals=TRUE checkothers=TRUE
MatchedLengths "Schematic Matched Net Lengths_30" [InNet('PA2')] p14: tolerance=2.54 checknetsindiffpair=FALSE checkdiffpairvsdiffpair=TRUE checkxsignals=TRUE checkothers=TRUE
MatchedLengths "Schematic Matched Net Lengths_29" [InNet('PI10')] p15: tolerance=2.54 checknetsindiffpair=FALSE checkdiffpairvsdiffpair=TRUE checkxsignals=TRUE checkothers=TRUE
MatchedLengths "Schematic Matched Net Lengths_28" [InNetClass('ULPI_D[0..7]')] p16: tolerance=2.54 checknetsindiffpair=FALSE checkdiffpairvsdiffpair=TRUE checkxsignals=TRUE checkothers=TRUE
MatchedLengths "Schematic Matched Net Lengths_27" [InNet('RD_P')] p17: tolerance=2.54 checknetsindiffpair=TRUE checkdiffpairvsdiffpair=FALSE checkxsignals=FALSE checkothers=FALSE
MatchedLengths "Schematic Matched Net Lengths_26" [InNet('PA7')] p18: tolerance=2.54 checknetsindiffpair=FALSE checkdiffpairvsdiffpair=TRUE checkxsignals=TRUE checkothers=TRUE
MatchedLengths "Schematic Matched Net Lengths_25" [InNet('PG14')] p19: tolerance=2.54 checknetsindiffpair=FALSE checkdiffpairvsdiffpair=TRUE checkxsignals=TRUE checkothers=TRUE
MatchedLengths "Schematic Matched Net Lengths_24" [InNet('PH4')] p20: tolerance=2.54 checknetsindiffpair=FALSE checkdiffpairvsdiffpair=TRUE checkxsignals=TRUE checkothers=TRUE
MatchedLengths "Schematic Matched Net Lengths_23" [InNet('PG11')] p21: tolerance=2.54 checknetsindiffpair=FALSE checkdiffpairvsdiffpair=TRUE checkxsignals=TRUE checkothers=TRUE
MatchedLengths "Schematic Matched Net Lengths_22" [InNet('PB6')] p22: tolerance=2.54 checknetsindiffpair=FALSE checkdiffpairvsdiffpair=TRUE checkxsignals=TRUE checkothers=TRUE
MatchedLengths "Schematic Matched Net Lengths_21" [InNet('PG8')] p23: tolerance=2.54 checknetsindiffpair=FALSE checkdiffpairvsdiffpair=TRUE checkxsignals=TRUE checkothers=TRUE
MatchedLengths "Schematic Matched Net Lengths_20" [InNet('TD_N')] p24: tolerance=2.54 checknetsindiffpair=TRUE checkdiffpairvsdiffpair=FALSE checkxsignals=FALSE checkothers=FALSE
MatchedLengths "Schematic Matched Net Lengths_19" [InNet('TD_P')] p25: tolerance=2.54 checknetsindiffpair=TRUE checkdiffpairvsdiffpair=FALSE checkxsignals=FALSE checkothers=FALSE
MatchedLengths "Schematic Matched Net Lengths_18" [InNet('PC4')] p26: tolerance=2.54 checknetsindiffpair=FALSE checkdiffpairvsdiffpair=TRUE checkxsignals=TRUE checkothers=TRUE
MatchedLengths "Schematic Matched Net Lengths_17" [InNet('PE2')] p27: tolerance=2.54 checknetsindiffpair=FALSE checkdiffpairvsdiffpair=TRUE checkxsignals=TRUE checkothers=TRUE
MatchedLengths "Schematic Matched Net Lengths_16" [InNet('PD13')] p28: tolerance=2.54 checknetsindiffpair=FALSE checkdiffpairvsdiffpair=TRUE checkxsignals=TRUE checkothers=TRUE
MatchedLengths "Schematic Matched Net Lengths_15" [InNet('PA1')] p29: tolerance=2.54 checknetsindiffpair=FALSE checkdiffpairvsdiffpair=TRUE checkxsignals=TRUE checkothers=TRUE
MatchedLengths "Schematic Matched Net Lengths_14" [InNet('PI14')] p30: tolerance=2.54 checknetsindiffpair=FALSE checkdiffpairvsdiffpair=TRUE checkxsignals=TRUE checkothers=TRUE
MatchedLengths "Schematic Matched Net Lengths_13" [InNet('PA6')] p31: tolerance=2.54 checknetsindiffpair=FALSE checkdiffpairvsdiffpair=TRUE checkxsignals=TRUE checkothers=TRUE
MatchedLengths "Schematic Matched Net Lengths_12" [InNet('PG13')] p32: tolerance=2.54 checknetsindiffpair=FALSE checkdiffpairvsdiffpair=TRUE checkxsignals=TRUE checkothers=TRUE
MatchedLengths "Schematic Matched Net Lengths_11" [InNet('PA4')] p33: tolerance=2.54 checknetsindiffpair=FALSE checkdiffpairvsdiffpair=TRUE checkxsignals=TRUE checkothers=TRUE
MatchedLengths "Schematic Matched Net Lengths_10" [InNet('PC1')] p34: tolerance=2.54 checknetsindiffpair=FALSE checkdiffpairvsdiffpair=TRUE checkxsignals=TRUE checkothers=TRUE
MatchedLengths "Schematic Matched Net Lengths_9" [InNet('PI9')] p35: tolerance=2.54 checknetsindiffpair=FALSE checkdiffpairvsdiffpair=TRUE checkxsignals=TRUE checkothers=TRUE
MatchedLengths "Schematic Matched Net Lengths_8" [InNet('PB2')] p36: tolerance=2.54 checknetsindiffpair=FALSE checkdiffpairvsdiffpair=TRUE checkxsignals=TRUE checkothers=TRUE
MatchedLengths "Schematic Matched Net Lengths_7" [InNetClass('PF[0..15]')] p37: tolerance=2.54 checknetsindiffpair=FALSE checkdiffpairvsdiffpair=TRUE checkxsignals=TRUE checkothers=TRUE
MatchedLengths "Schematic Matched Net Lengths_6" [InNetClass('FMC_A[0..11]')] p38: tolerance=2.54 checknetsindiffpair=FALSE checkdiffpairvsdiffpair=TRUE checkxsignals=TRUE checkothers=TRUE
MatchedLengths "Schematic Matched Net Lengths_5" [InNetClass('FMC_D[0..15]')] p39: tolerance=2.54 checknetsindiffpair=FALSE checkdiffpairvsdiffpair=TRUE checkxsignals=TRUE checkothers=TRUE
MatchedLengths "Schematic Matched Net Lengths_4" [InNetClass('LCD_B[0..7]')] p40: tolerance=2.54 checknetsindiffpair=FALSE checkdiffpairvsdiffpair=TRUE checkxsignals=TRUE checkothers=TRUE
MatchedLengths "Schematic Matched Net Lengths_3" [InNetClass('LCD_R[0..7]')] p41: tolerance=2.54 checknetsindiffpair=FALSE checkdiffpairvsdiffpair=TRUE checkxsignals=TRUE checkothers=TRUE
MatchedLengths "Schematic Matched Net Lengths_2" [InNet('RD_N')] p42: tolerance=2.54 checknetsindiffpair=TRUE checkdiffpairvsdiffpair=FALSE checkxsignals=FALSE checkothers=FALSE
MatchedLengths "Schematic Matched Net Lengths_1" [InNetClass('DCMI_D[0..7]')] p43: tolerance=2.54 checknetsindiffpair=FALSE checkdiffpairvsdiffpair=TRUE checkxsignals=TRUE checkothers=TRUE
MatchedLengths "Schematic Matched Net Lengths" [InNetClass('LCD_G[0..7]')] p44: tolerance=2.54 checknetsindiffpair=FALSE checkdiffpairvsdiffpair=TRUE checkxsignals=TRUE checkothers=TRUE
PolygonConnect PolygonConnect_CN8-1 [(ObjectKind = 'Pad') And (Name = 'CN8-1')] p1: connectstyle=Direct reliefconductorwidth=0.254 reliefentries=4 polygonreliefangle="90 Angle" airgapwidth=0.254
PolygonConnect "PolygonConnect_U21-5-6 To GND" [(ObjectKind = 'Pad') And (Name = 'U21-5') vs OnBottomLayer] p2: connectstyle=Relief reliefconductorwidth=0.15 reliefentries=4 polygonreliefangle="90 Angle" airgapwidth=0.25
PolygonConnect "PolygonConnect_U20-5-6 To GND" [(ObjectKind = 'Pad') And (Name = 'U20-5') vs OnBottomLayer] p3: connectstyle=Relief reliefconductorwidth=0.15 reliefentries=4 polygonreliefangle="90 Angle" airgapwidth=0.25
PolygonConnect "PolygonConnect_CN8-3 To GND" [(ObjectKind = 'Pad') And (Name = 'CN8-3') vs OnBottomLayer     or (Layer = 'F3') or     (Layer = 'F4')  or     (Layer = 'F6')] p4: connectstyle=Relief reliefconductorwidth=0.15 reliefentries=4 polygonreliefangle="90 Angle" airgapwidth=0.25
PolygonConnect "PolygonConnect_CN13-6 To GND" [(ObjectKind = 'Pad') And (Name = 'CN13-6') vs OnBottomLayer     or (Layer = 'F3') or     (Layer = 'F4')  or     (Layer = 'F6')  or     (Layer = 'F7')] p5: connectstyle=Relief reliefconductorwidth=0.15 reliefentries=4 polygonreliefangle="90 Angle" airgapwidth=0.25
PolygonConnect PolygonConnect_TEMPLATE18 [(ObjectKind = 'Poly') And (Name = 'TEMPLATE18')] p6: connectstyle=Direct reliefconductorwidth=0.254 reliefentries=4 polygonreliefangle="90 Angle" airgapwidth=0.254
PolygonConnect PolygonConnect_TEMPLATE15 [(ObjectKind = 'Poly') And (Name = 'TEMPLATE15')] p7: connectstyle=Direct reliefconductorwidth=0.254 reliefentries=4 polygonreliefangle="90 Angle" airgapwidth=0.254
PolygonConnect PolygonConnect_TEMPLATE16 [(ObjectKind = 'Poly') And (Name = 'TEMPLATE16')] p8: connectstyle=Direct reliefconductorwidth=0.254 reliefentries=4 polygonreliefangle="90 Angle" airgapwidth=0.254
PolygonConnect PolygonConnect_TEMPLATE14 [(ObjectKind = 'Poly') And (Name = 'TEMPLATE14')] p9: connectstyle=Direct reliefconductorwidth=0.254 reliefentries=4 polygonreliefangle="90 Angle" airgapwidth=0.254
PolygonConnect PolygonConnect_TEMPLATE12 [(ObjectKind = 'Poly') And (Name = 'TEMPLATE12')] p10: connectstyle=Direct reliefconductorwidth=0.254 reliefentries=4 polygonreliefangle="90 Angle" airgapwidth=0.254
PolygonConnect PolygonConnect_TEMPLATE9 [(ObjectKind = 'Poly') And (Name = 'TEMPLATE9')] p11: connectstyle=Direct reliefconductorwidth=0.254 reliefentries=4 polygonreliefangle="90 Angle" airgapwidth=0.254
PolygonConnect [All] p12: thpad.connectstyle=Relief thpad.reliefconductorwidth=0.15 thpad.reliefentries=4 thpad.polygonreliefangle="90 Angle" thpad.airgapwidth=0.15 smdpad.connectstyle=Relief smdpad.reliefconductorwidth=0.15 smdpad.reliefentries=4 smdpad.polygonreliefangle="90 Angle" smdpad.airgapwidth=0.15 via.connectstyle=Direct via.reliefconductorwidth=0.254 via.reliefentries=4 via.polygonreliefangle="90 Angle" via.airgapwidth=0.254
RoomDefinition RoomDefinition_iso100µm [False] p1: confinementstyle=ConfineIn formatcopy=TRUE lockcomponents=FALSE outline 16.675,17.825 16.9,17.6 21.1,17.6 21.1,12.9 21.043,12.957 16.677,12.957 16.677,17.477 16.85,17.65
RoutingLayers RoutingLayers_DiffPairs [InDifferentialPairClass('All Differential Pairs')] p1: top layer_v5=TRUE mid layer 1_v5=FALSE mid layer 2_v5=FALSE mid layer 3_v5=FALSE mid layer 4_v5=FALSE mid layer 5_v5=FALSE mid layer 6_v5=FALSE bottom layer_v5=TRUE
RoutingLayers [All] p2: top layer_v5=TRUE mid layer 1_v5=TRUE mid layer 2_v5=TRUE mid layer 3_v5=TRUE mid layer 4_v5=TRUE mid layer 5_v5=TRUE mid layer 6_v5=TRUE bottom layer_v5=TRUE
RoutingVias [All] p1: holewidth=0.15 width=0.35 viastyle="Through Hole" minholewidth=0.1 minwidth=0.25 maxholewidth=0.15 maxwidth=0.35
SolderMaskExpansion [All] p1: expansion=0.102 istentingtop=FALSE
Width [All] p1: maxlimit=1 minlimit=0.12 preferedwidth=0.12
26 further rules are at their usual default settings.

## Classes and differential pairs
component class Camera-Connectors: C1 C2 C3 P1 R1 R2 R3 R4 X1
component class "U_Arduino_ Connectors": C90 CN4 CN5 CN6 CN7 LD1 R59 R96 SB1 SB3 SB4 SB5 SB8
component class U_AUDIO: C4 C6 C7 C9 C30 C69 C70 C71 C72 C77 C78 C79 C80 C87 C88 C89 C92 C93 C102 C103 C104 C105 C106 C107 C115 CN1 CN10 CN11 JP3 JP4 R6 R7 R8 R9 R10 R22 R47 R76 R80 R83 R87 R102 R121 TP3 U1 U2 U11 U20 U21
component class U_Ethernet: C60 C63 C66 C67 C73 C74 C81 C82 C83 CN9 L2 R65 R66 R67 R68 R69 R70 R71 R73 R77 R78 R84 R88 R89 R90 R91 R92 R93 R94 R95 U9
component class U_LCD-43: C49 C53 C64 C65 C95 C96 C97 D5 L3 L4 L5 R74 R75 R81 R82 R85 U10 U19
component class U_Peripherals: B1 B2 C10 C25 CN2 CN3 R11 R12 R13 R14 R15 R16 R17 R18 R19 R39 SB2 SB6 SB7
component class U_QSPI: C38 R57 U3
component class U_SDRAM: C15 C16 C26 C27 C28 C31 C34 C42 C43 C45 C46 C50 C51 C52 R23 R24 R25 R26 R27 R36 R37 R40 R41 R43 R48 R49 R50 R51 R52 R53 R55 R56 U4
component class U_ST_LINK_V2-1: C29 C41 C61 C62 C68 C75 C76 C84 C85 C86 C91 C94 C98 C99 C100 C101 C108 C109 C113 C118 CN8 CN14 D1 D2 D3 D4 D6 JP1 JP2 LD2 LD7 R60 R72 R79 R86 R97 R98 R99 R100 R101 R105 R108 R109 R112 R118 R120 R127 R128 R129 R138 R139 SB9 SB10 SB11 SB12 SB13 SB14 SB15 SB16 SB17 T3 U6 U7 U8 U12 U13 U14 X4
component class U_STM32F7: C5 C8 C11 C12 C13 C14 C17 C18 C19 C20 C21 C22 C23 C24 C32 C33 C35 C36 C37 C39 C40 C44 C47 C48 C54 C55 C56 C57 C58 C59 L1 R5 R20 R21 R28 R29 R30 R31 R32 R33 R34 R35 R38 R42 R44 R45 R46 R54 R58 R61 R62 R63 R64 TP1 TP2 U5 X2 X3
component class U_USB_OTG_FS: C112 CN13 LD5 LD6 R116 R117 R119 R125 R126 R132 R133 R134 R135 R136 R137 SB18 T2 U16 U18
component class U_USB_OTG_HS: C110 C111 C114 C116 C117 C119 C120 C121 C122 C123 CN12 D7 L6 L7 LD3 LD4 R103 R104 R106 R107 R110 R111 R113 R114 R115 R122 R123 R124 R130 R131 R140 R141 T1 U15 U17 U22
net class ARD_A[0..5]: ARD_A0 ARD_A1 ARD_A2 ARD_A3 ARD_A4 ARD_A5
net class ARD_D[0..15]: ARD_D0 ARD_D1 ARD_D2 ARD_D3 ARD_D4 ARD_D5 ARD_D6 ARD_D7 ARD_D8 ARD_D9 ARD_D10 ARD_D11 ARD_D12 ARD_D13 ARD_D14 ARD_D15
net class DCMI_D[0..7]: DCMI_D0 DCMI_D1 DCMI_D2 DCMI_D3 DCMI_D4 DCMI_D5 DCMI_D6 DCMI_D7
net class FMC_A[0..11]: FMC_A0 FMC_A1 FMC_A2 FMC_A3 FMC_A4 FMC_A5 FMC_A6 FMC_A7 FMC_A8 FMC_A9 FMC_A10 FMC_A11
net class FMC_D[0..15]: FMC_D0 FMC_D1 FMC_D2 FMC_D3 FMC_D4 FMC_D5 FMC_D6 FMC_D7 FMC_D8 FMC_D9 FMC_D10 FMC_D11 FMC_D12 FMC_D13 FMC_D14 FMC_D15
net class LCD_B[0..7]: LCD_B0 LCD_B1 LCD_B2 LCD_B3 LCD_B4 LCD_B5 LCD_B6 LCD_B7
net class LCD_G[0..7]: LCD_G0 LCD_G1 LCD_G2 LCD_G3 LCD_G4 LCD_G5 LCD_G6 LCD_G7
net class LCD_R[0..7]: LCD_R0 LCD_R1 LCD_R2 LCD_R3 LCD_R4 LCD_R5 LCD_R6 LCD_R7
net class PA[0..15]: PA1 PA2 PA3 PA4 PA5 PA6 PA7 PA9 PA10 PA11 PA12 PA13 PA14
net class PB[0..15]: PB0 PB1 PB2 PB3 PB5 PB6 PB7 PB10 PB11 PB12 PB13
net class PC[0..15]: PC0 PC1 PC2 PC3 PC4 PC5 PC8 PC9 PC10 PC11 PC12 PC13 PC14 PC15
net class PD[0..15]: PD2 PD4 PD5 PD6 PD7 PD11 PD12 PD13
net class PE[0..15]: PE0 PE1 PE2 PE3
net class PF[0..15]: PF11
net class PG[0..15]: PG2 PG3 PG4 PG5 PG8 PG9 PG10 PG11 PG13 PG14 PG15
net class PH[0..15]: PH0 PH1 PH2 PH3 PH4 PH5 PH7 PH8 PH13 PH15
net class PI[0..15]: PI4 PI5 PI6 PI7 PI8 PI9 PI10 PI11 PI12 PI13 PI14
net class PJ[0..15]: PJ12
net class PK[0..7]: PK3 PK7
differential pair USB_FS1: +USB_FS1_P -USB_FS1_N
differential pair USB_HS: +USB_HS_P -USB_HS_N
differential pair TD: +TD_P -TD_N
differential pair RD: +RD_P -RD_N

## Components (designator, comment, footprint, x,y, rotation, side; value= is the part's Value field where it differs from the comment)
B1 "SW-PUSH-CMS_BLUE" BP1CMS 120,53.25 r270 top
B2 "SW-PUSH-CMS_BLACK" BP1CMS 120,37.25 r270 top
C1 "10uF" TAN-A 52.9,58.35 r90 top
C2 "100nF" 0402C 54.9,59.1 r90 top
C3 "100nF" 0402C 59.85,59.1 r90 top
C4 "100nF" 0402C 50.25,53 r180 top
C5 "100nF" 0402C 37,50.25 r180 top
C6 "22nF" 0402C 43,50 r270 top
C7 "100nF" 0402C 55,50.75 r0 top
C8 "1uF" TAN-A 27.5,48.25 r0 top
C9 "22nF" 0402C 51,47.75 r270 top
C10 "100nF" 0402C 119,47.75 r0 top
C11 "100nF" 0402C 27.5,46.5 r0 top
C12 "4.7pF_NPO_-+0.25pF_0402" 0402C 38.5,45.75 r0 top value=4.7pF
C13 "4.7pF_NPO_-+0.25pF_0402" 0402C 41,45.75 r180 top value=4.7pF
C14 "4.7uF" TAN-A 46.25,45.5 r0 top
C15 "100nF_X7R_10%_0402" 0402C 15.95,43.75 r270 top value=100nF
C16 "100nF_X7R_10%_0402" 0402C 16.95,43.75 r270 top value=100nF
C17 "1uF" TAN-A 24.75,42.75 r270 top
C18 "100nF" 0402C 30.5,43.5 r270 top
C19 "100nF" 0402C 31.75,43.5 r270 top
C20 "100nF" 0402C 34.25,43.5 r270 top
C21 "100nF" 0402C 35.5,43.5 r270 top
C22 "100nF" 0402C 36.75,43.5 r270 top
C23 "100nF" 0402C 41.75,43.5 r270 top
C24 "100nF" 0402C 27.5,41.25 r180 top
C25 "100nF" 0402C 122.25,42 r180 top
C26 "100nF_X7R_10%_0402" 0402C 8.7,40.45 r0 top value=100nF
C27 "100nF_X7R_10%_0402" 0402C 20.9,40.05 r180 top value=100nF
C28 "100nF_X7R_10%_0402" 0402C 20.9,39.05 r180 top value=100nF
C29 "10uF_X5R_10%_0805" 0805C 104,39 r90 top value=10uF
C30 "100nF" 0402C 1.7,37.75 r270 top
C31 "100nF_X7R_10%_0402" 0402C 8.7,37.45 r0 top value=100nF
C32 "100nF" 0402C 27.25,37.25 r0 top
C33 "100nF" 0402C 45.25,37.25 r180 top
C34 "100nF_X7R_10%_0402" 0402C 20.9,36.05 r180 top value=100nF
C35 "100nF" 0402C 27.25,35.75 r0 top
C36 "100nF" 0402C 45.25,36 r180 top
C37 "100nF" 0402C 45.25,35 r180 top
C38 "100nF_X7R_10%_0402" 0402C 69.947,34.924 r180 top value=100nF
C39 "100nF" 0402C 27.25,34.5 r0 top
C40 "100nF" 0402C 45.25,33.75 r180 top
C41 "10uF_X5R_10%_0805" 0805C 104,34.75 r270 top value=10uF
C42 "100nF_X7R_10%_0402" 0402C 8.7,32.85 r0 top value=100nF
C43 "100nF_X7R_10%_0402" 0402C 20.7,32.65 r180 top value=100nF
C44 "100nF" 0402C 27.25,33 r0 top
C45 "100nF_X7R_10%_0402" 0402C 20.7,31.65 r180 top value=100nF
C46 "100nF_X7R_10%_0402" 0402C 20.7,30.65 r180 top value=100nF
C47 "2.2uF" 1206C 26.5,31 r0 top
C48 "2.2uF" 1206C 46,30 r180 top
C49 "4.7uF" TAN-A 76.5,29.75 r180 top
C50 "100nF_X7R_10%_0402" 0402C 12.7,28 r180 top value=100nF
C51 "100nF_X7R_10%_0402" 0402C 15.3,27.05 r90 top value=100nF
C52 "100nF_X7R_10%_0402" 0402C 16.3,27.05 r90 top value=100nF
C53 "100nF" 0402C 75.75,27.75 r180 top
C54 "4.7uF" TAN-A 32,25.25 r90 top
C55 "100nF" 0402C 33.75,26.5 r90 top
C56 "100nF" 0402C 35,26.5 r90 top
C57 "100nF" 0402C 36.25,26.5 r90 top
C58 "100nF" 0402C 37.5,26.5 r90 top
C59 "100nF" 0402C 41.25,26.5 r90 top
C60 "100nF" 0402C 47.45,25.2 r270 top
C61 "100nF" 0402C 87,25 r270 top
C62 "1uF" 0603C 88.75,25 r270 top
C63 "10uF" TAN-A 37.427,23.29 r0 top
C64 "4.7uF_50V" 1206C 70,22.75 r90 top value=4.7uF
C65 "10nF" 0603C 72.75,22.25 r270 top
C66 "470pF" 0402C 51.5,22 r180 top
C67 "1uF" 0603C 54.85,22 r180 top
C68 "100nF" 0402C 84.25,22 r180 top
C69 "1uF" 0603C 18.26,20.49 r270 top
C70 "100nF" 0402C 19.75,20.5 r90 top
C71 "1uF" 0603C 21.25,20.5 r270 top
C72 "100nF" 0402C 24,19.25 r0 top
C73 "10uF" TAN-A 38.25,19.25 r0 top
C74 "100nF" 0402C 51.5,19.5 r180 top
C75 "1uF" 0603C 84.5,20.25 r180 top
C76 "100nF" 0402C 92.5,20.25 r0 top
C77 "100nF" 0402C 2.7,16.75 r270 top
C78 "2.2uF" 0603C 14.25,17 r180 top
C79 "4.7uF" 0603C 23.75,18 r0 top
C80 "2.2uF" 0603C 14.25,15.25 r180 top
C81 "100nF" 0402C 42.65,16 r90 top
C82 "100nF" 0402C 47,16 r270 top
C83 "100nF" 0402C 48,16 r270 top
C84 "100nF" 0402C 87.5,16.5 r0 top
C85 "100nF" 0402C 94.75,15.75 r90 top
C86 "1uF" 0603C 96.5,15.5 r270 top
C87 "2.2uF" 0603C 14.25,13.75 r0 top
C88 "4.7uF" 0603C 23.75,15 r180 top
C89 "1uF" 0603C 27.5,15 r0 top
C90 "[NA]" 0402C 66.5,13.75 r0 top
C91 "1uF" 0603C 87.25,14.5 r0 top
C92 "100nF" 0402C 14.25,12.25 r180 top
C93 "4.7uF" 0603C 23.75,13.25 r0 top
C94 "10nF" 0603C 91.75,12.5 r0 top
C95 "100nF" 0603C 76.25,11.25 r90 top
C96 "10nF" 0603C 78.25,11.25 r90 top
C97 "4.7uF_16V" 1206C 80.75,10.75 r270 top value=4.7uF
C98 "100nF" 0402C 103,11.75 r270 top
C99 "10pF" 0402C 105.75,11.75 r270 top
C100 "10pF" 0402C 107,11.75 r270 top
C101 "100nF" 0402C 110.75,11.75 r270 top
C102 "100nF" 0402C 14.75,10.25 r270 top
C103 "100nF" 0402C 16.5,10.25 r270 top
C104 "4.7uF" 0603C 18,10.25 r270 top
C105 "4.7uF" 0603C 19.75,10.25 r90 top
C106 "1uF" 0603C 21.5,10.25 r270 top
C107 "1uF" 0603C 23.25,10.25 r270 top
C108 "10uF_X5R_10%_0603" 0603C 32.25,7.5 r0 top value=10uF
C109 "100nF" 0402C 112.75,8.25 r180 top
C110 "100nF" 0402C 73.75,3.75 r180 top
C111 "100nF" 0402C 75.75,4.5 r270 top
C112 "4.7uF_X5R_10%_0603" 0603C 85,1.25 r270 top value=4.7uF
C113 "100nF" 0402C 98.75,2.25 r270 top
C114 "4.7uF_X5R_10%_0603" 0603C 59.5,-0.25 r180 top value=4.7uF
C115 "100nF" 0402C 5.5,-1.75 r90 top
C116 "100nF" 0402C 69,-1.75 r90 top
C117 "100nF" 0402C 70.25,-1.75 r270 top
C118 "100nF" 0402C 108.5,-2.5 r270 top
C119 "2.2uF_X7R_10%_0805" 0805C 71,-4.25 r0 top value=2.2uF
C120 "100nF" 0402C 63.75,-7.25 r270 top
C121 "100nF" 0402C 72.25,-7.75 r180 top
C122 "100nF" 0402C 61.75,-9.75 r270 top
C123 "100nF" 0402C 74.75,-11 r180 top
CN1 "RCA_SMD" RCA_SMD 41.075,59.875 r270 top
CN2 "F206A-2*04MGF-A" SSM-104-L-DH 21.5,58.5 r90 top
CN3 "PJS008-2003-1" PJS008-2003-1 89.025,67.325 r90 top
CN4 "F201-1*08MGF-W1-LBE" F201-1*08MGF-W1-BA 61.74,45.71 r270 top
CN5 "F201-1*06MGF-W1-LBE" F201-1*06MGF-W1-BA 110,48.25 r90 top
CN6 "F201-1*08MGF-W1-LBE" F201-1*08MGF-W1-BA 110,27.93 r90 top
CN7 "F201-1*10MGF-W1-LBE" F201-1*10MGF-W1-BA 61.74,21.326 r270 top
CN8 "Header 4" "HEADER 4" 121.7,5.85 r270 top
CN9 "HR961160C" RJ45_HR961160C 46.186,-8.814 r0 top
CN10 "PJ3028B-3_GR" PJ3028B 10.8,-4.25 r90 top
CN11 "PJ3028B-3_BE" PJ3028B 22,-4.25 r90 top
CN12 "USB-MICRO-AB" USB-MICRO-AB 67.757,-8.318 r90 top
CN13 "USB-MICRO-AB" USB-MICRO-AB 85.25,-8.25 r90 top locked
CN14 "USB-MINI-typeB" USB-MINI-B-SMD 106.5,-8.5 r180 top locked
D1 "BAT60JFILM" SOD323/A 102.75,31.5 r0 top
D2 "BAT60JFILM" SOD323/A 98.75,21.25 r180 top
D3 "BAT60JFILM" SOD323/A 102.75,21.25 r0 top
D4 "BAT60JFILM" SOD323/A 102.75,18.75 r0 top
D5 "STPS1L40M" DO216-AA 70,17.75 r270 top
D6 "BAT60JFILM" SOD323/A 116.75,5 r0 top
D7 "ESDA14V2-2BF3" BGA4_1X1 66,-6 r180 top
FX4 "Comment" FIX3.25NMET 1,63.25 r0 top locked
IMP1 "Comment" "IMPEDANCE BOARD 8" -110.75,98.425 r0 top
JP1 "TSM-104-01-x-DV" TSM-104-01-X-DV 120.25,25 r270 top
JP2 "TSM-102-01-F-SH-A" TSM-102-01-F-SH-A 118.6,12.655 r0 top
JP3 "Jumper 2 pins" SIP2/2.54 30.1,-8.25 r270 top
JP4 "Jumper 2 pins" SIP2/2.54 33.3,-8.25 r270 top
L1 "FCM1608KF-601T03" 0603L 27.5,45 r0 top value=100uH
L2 "BLM18PG121SN1D" 0603L 38.5,21 r180 top value=100uH
L3 "4.7uH 1A 30%" 1210L 76.5,15.75 r0 top
L4 "FCM1608KF-601T03" 0603L 73.5,12 r0 top value=100uH
L5 "FCM1608KF-601T03" 0603L 73.5,10 r0 top value=100uH
L6 "BLM18PG121SN1D" 0603L 71.5,-6.25 r180 top value=100uH
L7 "BLM18PG121SN1D" 0603L 74.75,-9.25 r180 top value=100uH
LD1 "LED, green" 0603D 121,31.75 r0 top
LD2 "LED, red" 0603D 121.25,17.75 r0 top
LD3 "LED, red" 0603D 60,-9.75 r90 top
LD4 "LED, green" 0603D 77.5,-9.75 r90 top
LD5 "LED, green" 0603D 92.5,-9.75 r90 top
LD6 "LED, red" 0603D 94.75,-9.75 r90 top
LD7 "LD_BICOLOR_CMS" HSMF-A201 116,-9.75 r90 top
P1 "FPU330ZH-BT1D3-CA" FPU330ZH-BT1D3-CA 62,64.75 r180 top
R1 "100_1%_0402" 0402R 56,59.1 r90 top value=100
R2 "100_1%_0402" 0402R 57.1,59.1 r90 top value=100
R3 "100_1%_0402" 0402R 58.65,59.1 r90 top value=100
R4 "10K_1%_0402" 0402R 55.8,53.15 r90 top value=10K
R5 "10K_1%_0402" 0402R 34.5,50.25 r180 top value=10K
R6 "75" 0402R 40.75,50.75 r0 top
R7 "100" 0402R 44.5,50 r90 top
R8 "[NA]" 0402R 51,50.75 r90 top
R9 "1M" 0402R 48,48.25 r0 top
R10 "100" 0402R 52.5,47.75 r90 top
R11 "0_5%_0402" 0402R 81.25,47.75 r90 top value=0
R12 "[NA]" 0402R 82.5,47.75 r270 top
R13 "47K_1%_0402" 0402R 83.75,47.75 r270 top value=47K
R14 "47K_1%_0402" 0402R 85,47.75 r270 top value=47K
R15 "47K_1%_0402" 0402R 89.25,47.75 r270 top value=47K
R16 "47K_1%_0402" 0402R 90.5,47.75 r270 top value=47K
R17 "47K_1%_0402" 0402R 91.75,47.75 r270 top value=47K
R18 "10K" 0402R 121.75,49 r0 top
R19 "10K" 0402R 121.75,47.75 r0 top
R20 "10K" 0402R 31.75,46 r0 top
R21 "0" 0603R-GS 50.75,44.75 r0 top
R22 "1M" 0402R 55.25,46 r0 top
R23 "10K_1%_0402" 0402R 11.4,43.75 r90 top value=10K
R24 "10K_1%_0402" 0402R 12.4,43.75 r90 top value=10K
R25 "10K_1%_0402" 0402R 14.95,43.75 r90 top value=10K
R26 "10K_1%_0402" 0402R 17.95,43.75 r90 top value=10K
R27 "10K_1%_0402" 0402R 18.95,43.75 r90 top value=10K
R28 "0" 0603R-GS 27.5,43 r180 top
R29 "100" 0402R 33,43.5 r90 top
R30 "100_1%_0402" 0402R 38,43.5 r270 top value=100
R31 "0" 0402R 39.25,43.5 r270 top
R32 "0" 0402R 40.5,43.5 r270 top
R33 "100" 0402R 43,43.5 r90 top
R34 "10K_1%_0402" 0402R 45.25,43.75 r0 top value=10K
R35 "[NA]" 0402R 45.25,42.75 r180 top
R36 "10K_1%_0402" 0402R 8.7,41.45 r180 top value=10K
R37 "10K_1%_0402" 0402R 20.9,42.05 r0 top value=10K
R38 "10K_1%_0402" 0402R 45.25,41.75 r180 top value=10K
R39 "10K_1%_0402" 0402R 125.071,42.421 r270 top value=10K
R40 "10K_1%_0402" 0402R 6.4,40.15 r90 top value=10K
R41 "10K_1%_0402" 0402R 20.9,41.05 r0 top value=10K
R42 "[NA]" 0402R 45.25,40.75 r180 top
R43 "10K_1%_0402" 0402R 8.7,39.45 r180 top value=10K
R44 "0" 0402R 27.25,38.75 r0 top
R45 "10K_1%_0402" 0402R 45.25,39.75 r180 top value=10K
R46 "2K7_1%_0402" 0402R 49,38.75 r0 top value=2K7
R47 "10K" 0402R 3.1,37.75 r90 top
R48 "10K_1%_0402" 0402R 6.4,37.35 r270 top value=10K
R49 "10K_1%_0402" 0402R 8.7,38.45 r180 top value=10K
R50 "10K_1%_0402" 0402R 20.9,38.05 r0 top value=10K
R51 "10K_1%_0402" 0402R 23.9,37.75 r0 top value=10K
R52 "10K_1%_0402" 0402R 8.7,36.45 r180 top value=10K
R53 "10K_1%_0402" 0402R 20.9,37.05 r0 top value=10K
R54 "2K7_1%_0402" 0402R 49,36.5 r0 top value=2K7
R55 "10K_1%_0402" 0402R 8.7,35.45 r0 top value=10K
R56 "10K_1%_0402" 0402R 20.9,34.75 r180 top value=10K
R57 "10K_1%_0402" 0402R 73.25,34.75 r180 top value=10K
R58 "100" 0402R 45.25,32.25 r0 top
R59 "510_1%_0402" 0402R 117.5,31.75 r180 top value=510
R60 "10K_1%_0402" 0402R 92.5,29.5 r0 top value=10K
R61 "2K7_1%_0402" 0402R 27.5,28 r180 top value=2K7
R62 "2K7_1%_0402" 0402R 27.5,26.75 r180 top value=2K7
R63 "[NA]" 0402R 38.75,26.5 r90 top
R64 "0" 0402R 40,26.5 r90 top
R65 "1K5" 0402R 42.04,23.35 r180 top
R66 "33" 0402R 42.7,25.225 r90 top
R67 "4K7" 0402R 45.436,25.186 r90 top
R68 "4K7" 0402R 46.436,25.186 r270 top
R69 "33" 0402R 48.436,25.186 r90 top
R70 "4K7" 0402R 49.436,25.186 r90 top
R71 "33" 0402R 51.5,24.5 r0 top
R72 "100K_1%_0402" 0402R 96,25 r90 top value=100K
R73 "4K7" 0402R 51.5,23.25 r0 top
R74 "4K7" 0402R 55,23.5 r0 top
R75 "10_1%_0805" 0805R 78.75,23 r0 top value=10
R76 "0" 0402R 13.9,21.05 r0 top
R77 "4K7" 0402R 41.975,21.289 r180 top
R78 "100" 0402R 51.5,20.75 r180 top
R79 "2K7" 0402R 89.5,20.25 r180 top
R80 "[NA]" 0402R 13.9,19.85 r0 top
R81 "0" 0402R 73,19.75 r180 top
R82 "100K" 0402R 79.5,20 r90 top
R83 "0" 0402R 13.9,18.6 r0 top
R84 "12K1" 0603R 51.5,18.25 r0 top
R85 "4K7" 0402R 73,18.5 r180 top
R86 "1K" 0402R 117.5,17.75 r0 top
R87 "10K" 0402R 23.5,16.5 r0 top
R88 "10K" 0402R 39.5,16 r270 top
R89 "330" 0402R 41.25,16 r270 top
R90 "50" 0402R 43.75,16 r90 top value=49.9
R91 "50" 0402R 45.8,16 r90 top value=49.9
R92 "50" 0402R 49,16 r270 top value=49.9
R93 "50" 0402R 50,16 r270 top value=49.9
R94 "330" 0402R 51,16 r270 top
R95 "10K" 0402R 52.75,16 r270 top
R96 "0" 0402R 66.5,15 r0 top
R97 "4K7_1%_0402" 0402R 99.25,11.75 r270 top value=4K7
R98 "4K7_1%_0402" 0402R 100.5,11.75 r270 top value=4K7
R99 "100K_1%_0402" 0402R 101.75,11.75 r90 top value=100K
R100 "[NA]" 0402R 108.25,11.75 r270 top
R101 "10K_1%_0402" 0402R 109.5,11.75 r270 top value=10K
R102 "20" 0402R 13.5,10.25 r90 top
R103 "[NA]" 0402R 64.25,7.25 r0 top
R104 "0_5%_0402" 0402R 64.25,6 r180 top value=0
R105 "100K_1%_0402" 0402R 112.75,6.5 r180 top value=100K
R106 "[NA]" 0402R 64.25,4.75 r0 top
R107 "0_5%_0402" 0402R 73.75,5 r0 top value=0
R108 "2K7_1%_0402" 0402R 112.75,5 r0 top value=2K7
R109 "0" 0402R 112.75,3.75 r0 top
R110 "0_5%_0402" 0402R 64.25,3.5 r180 top value=0
R111 "[NA]" 0402R 64.25,2.25 r0 top
R112 "4K7_1%_0402" 0402R 112.75,2.5 r180 top value=4K7
R113 "0_5%_0402" 0402R 64.25,1 r180 top value=0
R114 "100_1%_0402" 0402R 73.5,1.5 r180 top value=100
R115 "8K06_1%_0402" 0402R 73.5,0.25 r0 top value=8K06
R116 "10K_1%_0402" 0402R 90.75,1.5 r0 top value=10K
R117 "0_5%_0402" 0402R 90.75,0.25 r180 top value=0
R118 "100_1%_0402" 0402R 112.75,1.25 r180 top value=100
R119 "0_5%_0402" 0402R 90.75,-1 r0 top value=0
R120 "10K_1%_0402" 0402R 112.75,-0.25 r180 top value=10K
R121 "20" 0402R 4.25,-1.75 r270 top
R122 "3K3" 0402R 59.75,-2 r0 top
R123 "820_1%_0805" 0805R 73,-1.75 r180 top value=820
R124 "47K_1%_0402" 0402R 75.5,-1.75 r270 top value=47K
R125 "0" 0402R 81.6,-2.35 r0 top
R126 "47K_1%_0402" 0402R 90.75,-2.25 r0 top value=47K
R127 "100_1%_0402" 0402R 103,-1.75 r180 top value=100
R128 "1K5_1%_0402" 0402R 107.25,-2.5 r270 top value=1K5
R129 "36K_1%_0402" 0402R 112.75,-1.75 r0 top value=36K
R130 "0" 0402R 59.75,-3.25 r180 top
R131 "100K" 0402R 75.5,-4.5 r270 top
R132 "0" 0402R 81.6,-3.55 r0 top
R133 "0" 0402R 81.6,-4.75 r0 top
R134 "47K_1%_0402" 0402R 88.25,-5 r270 top value=47K
R135 "100K" 0402R 89.25,-5 r270 top
R136 "330_1%_0603" 0603R 91.5,-5.75 r180 top value=330
R137 "620_1%_0603" 0603R 95.75,-5.75 r0 top value=620
R138 "330_1%_0402" 0402R 115.25,-6 r270 top value=330
R139 "330_1%_0402" 0402R 116.75,-6 r90 top value=330
R140 "620_1%_0603" 0603R 58,-9.75 r90 top value=620
R141 "330_1%_0402" 0402R 79.25,-10 r90 top value=330
SB1 "Solder Bridge OFF" JP2_SMD 103.75,54.75 r0 top
SB2 "Solder Bridge OFF" JP2_SMD 21,52 r0 top
SB3 "Solder Bridge ON" JP2_SMD 103.75,53.25 r0 top
SB4 "Solder Bridge OFF" JP2_SMD 103.75,51.75 r0 top
SB5 "Solder Bridge ON" JP2_SMD 103.75,50.25 r0 top
SB6 "Solder Bridge ON" JP2_SMD 119,49 r0 top
SB7 "Solder Bridge ON" JP2_SMD 117.75,42 r180 top
SB8 "Solder Bridge ON" JP2_SMD 66.75,20 r180 top
SB9 "Solder Bridge OFF" JP2_SMD 95.5,20.25 r0 top
SB10 "Solder Bridge ON" JP2_SMD 88.75,18 r180 top
SB11 "Solder Bridge OFF" JP2_SMD 104.25,11.75 r270 top
SB12 "Solder Bridge ON" JP2_SMD 96,8.75 r0 top
SB13 "Solder Bridge ON" JP2_SMD 96,7.25 r0 top
SB14 "Solder Bridge ON" JP2_SMD 96,5.75 r180 top
SB15 "Solder Bridge ON" JP2_SMD 96,4.25 r180 top
SB16 "Solder Bridge ON" JP2_SMD 96,2.75 r180 top
SB17 "Solder Bridge ON" JP2_SMD 96,1.25 r180 top
SB18 "Solder Bridge ON" JP2_SMD 87,-5 r270 top
T1 "9013-SOT23" SOT23 78,-3.75 r0 top
T2 "9013-SOT23" SOT23 94.75,-2.25 r90 top
T3 "9013-SOT23" SOT23 116,-2.75 r0 top
TP1 "TP" SMDTEST-1MM 32,48.25 r0 top
TP2 "TP" SMDTEST-1MM 43,48 r0 top
TP3 "Test point 1 pin with hole" SIP1/2.54 0,0 r0 top
U1 "74LVC1G04SE" SOT353 47.25,50.75 r270 top
U2 "74LVC1G04SE" SOT353 55,48.5 r270 top
U3 "W25Q128JVEIQ" W-PDFN-8_8X6_P127 73.175,39.13 r180 top
U4 "IS42S32400F-6BL (ISSI)" FBGA90_0R8_8X13 14.7,35.25 r0 top
U5 "STM32F746NGH6" BGA216_0R8_13X13_SKT 36,35.25 r270 top
U6 "LD1117S50TR" SOT-223 97.5,35.75 r180 top
U7 "LD39050PU33R" DFN6_3X3 84.5,25 r180 top
U8 "ST890CDR" SO-8 92.5,25 r180 top
U9 "LAN8742A-CZ-TR" QFN24_0R5_4X4 46.572,20.539 r180 top
U10 "STLD40DPUR" QFN8_0R65_3X3_ST 76.5,20 r90 top
U11 "WM8994ECS/R" BGA72_0R5_4R5X4 19,15.25 r270 top
U12 "LD3985M33R" SOT23-5L 91.5,15.5 r270 top
U13 "LD1117S18TR" SOT-223 33.25,13.75 r90 top
U14 "STM32F103CBT6" "QFP48 7X7" 105.25,4.5 r270 top
U15 "USB3320C-EZK" QFN32_0R5_5X5 69,2.75 r270 top
U16 "STMPS2141STR" SOT23-5L 87.5,-0.75 r0 top
U17 "STMPS2151STR" SOT23-5L 63.75,-2.25 r270 top
U18 "EMIF02-USB03F2" "FLIP CHIP" 84.5,-2.5 r0 top
U19 "GJX043A6 -40D Y" "LCD_Kunjian_ HT043C_40P_P080_FLEX_FOLDED" 61.8,27.27 r180 bottom locked
U20 "IMP34DT05TR" HCLGA_3X4X1_4LD 1.575,37.75 r0 bottom
U21 "IMP34DT05TR" HCLGA_3X4X1_4LD 1.575,16.8 r0 bottom
U22 "ESD7383NCTBG" ESD_WLCSP4_CASE-567CB_0P80X0P80_P040 68.1,-5.65 r90 top
X1 "NZ2520SH-24.00M" NZ2520SH_4P 56.6,55.8 r0 top
X2 "NZ2520SH-25.00M" NZ2520SH_4P 35.3,47.25 r270 top
X3 "NX3215SA-32.768K" XTAL_2SM_3R2X1R5 39.7,48 r180 top
X4 "NX3225GD-8.00M" XTAL_2SM_3R2X2R5 105.75,15.5 r0 top

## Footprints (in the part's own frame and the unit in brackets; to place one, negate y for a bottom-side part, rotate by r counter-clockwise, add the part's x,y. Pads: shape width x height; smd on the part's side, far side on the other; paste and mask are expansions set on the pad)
0402C [mm]
  rect 0.962x0.762 smd: 1(-0.6,0) 2(0.6,0)
  silkscreen extent -1.2,-0.5 1.2,0.5
0402R [mm]
  rect 0.962x0.762 smd: 1(-0.6,0) 2(0.6,0)
  silkscreen extent -1.2,-0.5 1.2,0.5
0603C [mm]
  rect 1.1x1.2 smd: 1(-0.85,0) 2(0.85,0)
  silkscreen extent -0.85,-0.8 0.86,0.8
0603D [mm]
  rect 1.1x1.2 smd: 1(-0.85,0) 2(0.85,0)
  silkscreen extent -0.86,-0.8 1.67,0.8
0603L [mm]
  rect 1.1x1.2 smd: 1(-0.85,0) 2(0.85,0)
  silkscreen extent -0.85,-0.8 0.86,0.8
0603R [mm]
  rect 1.1x1.2 smd: 1(-0.85,0) 2(0.85,0)
  silkscreen extent -0.85,-0.8 0.86,0.8
0603R-GS [mm]
  rect 1.25x1.2 smd: 1(-0.775,0) 2(0.775,0)
  silkscreen extent -0.86,-0.8 0.84,0.79
0805C [mil]
  rect 40x50 smd: 1(40,0) 2(-40,0)
  silkscreen extent -70,-35 70,35
0805R [mil]
  rect 40x50 smd: 1(40,0) 2(-40,0)
  silkscreen extent -70,-35 70,35
1206C [mil]
  rect 50x72 smd: 1(-55,0) 2(55,0)
  silkscreen extent -94,-54 94,54
1210L [mm]
  rect 1.6x3.2 smd: 1(1.524,0) 2(-1.524,0)
  silkscreen extent -3.05,-2.03 3.05,2.03
BGA4_1X1 [mm]
  round 0.22 smd: A1(-0.2,0.2) A2(0.2,0.2) B1(-0.2,-0.2) B2(0.2,-0.2)
  silkscreen extent -1,-0.6 0.6,0.9
BGA72_0R5_4R5X4 [mm]
  round 0.25 smd: A1(-2,1.75) A2(-1.5,1.75) A3(-1,1.75) A4(-0.5,1.75) A5(0,1.75) A6(0.5,1.75) A7(1,1.75) A8(1.5,1.75) A9(2,1.75) B1(-2,1.25) B2(-1.5,1.25) B3(-1,1.25) B4(-0.5,1.25) B5(0,1.25) B6(0.5,1.25) B7(1,1.25) B8(1.5,1.25) B9(2,1.25) C1(-2,0.75) C2(-1.5,0.75) C3(-1,0.75) C4(-0.5,0.75) C5(0,0.75) C6(0.5,0.75) C7(1,0.75) C8(1.5,0.75) C9(2,0.75) D1(-2,0.25) D2(-1.5,0.25) D3(-1,0.25) D4(-0.5,0.25) D5(0,0.25) D6(0.5,0.25) D7(1,0.25) D8(1.5,0.25) D9(2,0.25) E1(-2,-0.25) E2(-1.5,-0.25) E3(-1,-0.25) E4(-0.5,-0.25) E5(0,-0.25) E6(0.5,-0.25) E7(1,-0.25) E8(1.5,-0.25) E9(2,-0.25) F1(-2,-0.75) F2(-1.5,-0.75) F3(-1,-0.75) F4(-0.5,-0.75) F5(0,-0.75) F6(0.5,-0.75) F7(1,-0.75) F8(1.5,-0.75) F9(2,-0.75) G1(-2,-1.25) G2(-1.5,-1.25) G3(-1,-1.25) G4(-0.5,-1.25) G5(0,-1.25) G6(0.5,-1.25) G7(1,-1.25) G8(1.5,-1.25) G9(2,-1.25) H1(-2,-1.75) H2(-1.5,-1.75) H3(-1,-1.75) H4(-0.5,-1.75) H5(0,-1.75) H6(0.5,-1.75) H7(1,-1.75) H8(1.5,-1.75) H9(2,-1.75)
  silkscreen extent -2.85,-2.25 2.5,2.6
BGA216_0R8_13X13_SKT [mm]
  oct 0.35x0.35 smd: A1(-5.6,5.6) A2(-4.8,5.6) A3(-4,5.6) A4(-3.2,5.6) A5(-2.4,5.6) A6(-1.6,5.6) A7(-0.8,5.6) A8(0,5.6) A9(0.8,5.6) A10(1.6,5.6) A11(2.4,5.6) A12(3.2,5.6) A13(4,5.6) A14(4.8,5.6) A15(5.6,5.6) B1(-5.6,4.8) B2(-4.8,4.8) B3(-4,4.8) B4(-3.2,4.8) B5(-2.4,4.8) B6(-1.6,4.8) B7(-0.8,4.8) B8(0,4.8) B9(0.8,4.8) B10(1.6,4.8) B11(2.4,4.8) B12(3.2,4.8) B13(4,4.8) B14(4.8,4.8) B15(5.6,4.8) C1(-5.6,4) C2(-4.8,4) C3(-4,4) C4(-3.2,4) C5(-2.4,4) C6(-1.6,4) C7(-0.8,4) C8(0,4) C9(0.8,4) C10(1.6,4) C11(2.4,4) C12(3.2,4) C13(4,4) C14(4.8,4) C15(5.6,4) D1(-5.6,3.2) D2(-4.8,3.2) D3(-4,3.2) D4(-3.2,3.2) D5(-2.4,3.2) D6(-1.6,3.2) D7(-0.8,3.2) D8(0,3.2) D9(0.8,3.2) D10(1.6,3.2) D11(2.4,3.2) D12(3.2,3.2) D13(4,3.2) D14(4.8,3.2) D15(5.6,3.2) E1(-5.6,2.4) E2(-4.8,2.4) E3(-4,2.4) E4(-3.2,2.4) E5(-2.4,2.4) E6(-1.6,2.4) E7(-0.8,2.4) E8(0,2.4) E9(0.8,2.4) E10(1.6,2.4) E11(2.4,2.4) E12(3.2,2.4) E13(4,2.4) E14(4.8,2.4) E15(5.6,2.4) F1(-5.6,1.6) F2(-4.8,1.6) F3(-4,1.6) F4(-3.2,1.6) F5(-2.4,1.6) F6(-1.6,1.6) F7(-0.8,1.6) F8(0,1.6) F9(0.8,1.6) F10(1.6,1.6) F11(2.4,1.6) F12(3.2,1.6) F13(4,1.6) F14(4.8,1.6) F15(5.6,1.6) G1(-5.6,0.8) G2(-4.8,0.8) G3(-4,0.8) G4(-3.2,0.8) G5(-2.4,0.8) G6(-1.6,0.8) G10(1.6,0.8) G11(2.4,0.8) G12(3.2,0.8) G13(4,0.8) G14(4.8,0.8) G15(5.6,0.8) H1(-5.6,0) H2(-4.8,0) H3(-4,0) H4(-3.2,0) H5(-2.4,0) H6(-1.6,0) H10(1.6,0) H11(2.4,0) H12(3.2,0) H13(4,0) H14(4.8,0) H15(5.6,0) J1(-5.6,-0.8) J2(-4.8,-0.8) J3(-4,-0.8) J4(-3.2,-0.8) J5(-2.4,-0.8) J6(-1.6,-0.8) J10(1.6,-0.8) J11(2.4,-0.8) J12(3.2,-0.8) J13(4,-0.8) J14(4.8,-0.8) J15(5.6,-0.8) K1(-5.6,-1.6) K2(-4.8,-1.6) K3(-4,-1.6) K4(-3.2,-1.6) K5(-2.4,-1.6) K6(-1.6,-1.6) K7(-0.8,-1.6) K8(0,-1.6) K9(0.8,-1.6) K10(1.6,-1.6) K11(2.4,-1.6) K12(3.2,-1.6) K13(4,-1.6) K14(4.8,-1.6) K15(5.6,-1.6) L1(-5.6,-2.4) L2(-4.8,-2.4) L3(-4,-2.4) L4(-3.2,-2.4) L5(-2.4,-2.4) L6(-1.6,-2.4) L7(-0.8,-2.4) L8(0,-2.4) L9(0.8,-2.4) L10(1.6,-2.4) L11(2.4,-2.4) L12(3.2,-2.4) L13(4,-2.4) L14(4.8,-2.4) L15(5.6,-2.4) M1(-5.6,-3.2) M2(-4.8,-3.2) M3(-4,-3.2) M4(-3.2,-3.2) M5(-2.4,-3.2) M6(-1.6,-3.2) M7(-0.8,-3.2) M8(0,-3.2) M9(0.8,-3.2) M10(1.6,-3.2) M11(2.4,-3.2) M12(3.2,-3.2) M13(4,-3.2) M14(4.8,-3.2) M15(5.6,-3.2) N1(-5.6,-4) N2(-4.8,-4) N3(-4,-4) N4(-3.2,-4) N5(-2.4,-4) N6(-1.6,-4) N7(-0.8,-4) N8(0,-4) N9(0.8,-4) N10(1.6,-4) N11(2.4,-4) N12(3.2,-4) N13(4,-4) N14(4.8,-4) N15(5.6,-4) P1(-5.6,-4.8) P2(-4.8,-4.8) P3(-4,-4.8) P4(-3.2,-4.8) P5(-2.4,-4.8) P6(-1.6,-4.8) P7(-0.8,-4.8) P8(0,-4.8) P9(0.8,-4.8) P10(1.6,-4.8) P11(2.4,-4.8) P12(3.2,-4.8) P13(4,-4.8) P14(4.8,-4.8) P15(5.6,-4.8) R1(-5.6,-5.6) R2(-4.8,-5.6) R3(-4,-5.6) R4(-3.2,-5.6) R5(-2.4,-5.6) R6(-1.6,-5.6) R7(-0.8,-5.6) R8(0,-5.6) R9(0.8,-5.6) R10(1.6,-5.6) R11(2.4,-5.6) R12(3.2,-5.6) R13(4,-5.6) R14(4.8,-5.6) R15(5.6,-5.6)
  silkscreen extent -7.4,-6.5 6.5,7.4
BP1CMS [mm]
  rect 1.52x2.16 smd: 1(-2.25,-4.55) 2(2.25,-4.55) 3(2.25,4.55) 4(-2.25,4.55)
  silkscreen extent -3.4,-5.1 3.4,5.12
DFN6_3X3 [mm]
  rect 0.5x0.8 smd: 1(-0.95,-1.4) 2(0,-1.4) 3(0.95,-1.4) 4(0.95,1.4) 5(0,1.4) 6(-0.95,1.4)
  rect 2.5x1.75 smd: 7(0,0)
  silkscreen extent -1.8,-1.9 1.5,1.5
DO216-AA [mm]
  rect 1.38x0.75 smd: 1(2.01,0)
  rect 1.82x2.03 smd: 2(-0.3,0)
  Top region: -0.3,0.5 -0.3,0.95 0.9,0.95 0.9,-0.95 -0.3,-0.95 -0.3,-0.5 -1.7,-0.5 -1.7,0.5
  silkscreen extent -2.2,-1.4 3.1,1.4
ESD_WLCSP4_CASE-567CB_0P80X0P80_P040 [mm]
  round 0.25 smd paste+0 mask+0.038: A1(-0.2,0.2) A2(0.2,0.2) B1(-0.2,-0.2) B2(0.2,-0.2)
  silkscreen extent -0.55,-0.43 0.43,0.55, body extent -0.4,-0.4 0.4,0.4, height 0.64
F201-1*06MGF-W1-BA [mm]
  rect 1.02x3 smd: 1(-6.35,-1.5) 2(-3.81,1.5) 3(-1.27,-1.5) 4(1.27,1.5) 5(3.81,-1.5) 6(6.35,1.5)
  silkscreen extent -9.17,-2.91 7.87,1.27
F201-1*08MGF-W1-BA [mm]
  rect 1.02x3 smd: 1(-8.89,-1.5) 2(-6.35,1.5) 3(-3.81,-1.5) 4(-1.27,1.5) 5(1.27,-1.5) 6(3.81,1.5) 7(6.35,-1.5) 8(8.89,1.5)
  silkscreen extent -12.13,-1.27 10.41,1.27
F201-1*10MGF-W1-BA [mm]
  rect 1.02x3 smd: 1(-11.43,-1.5) 2(-8.89,1.5) 3(-6.35,-1.5) 4(-3.81,1.5) 5(-1.27,-1.5) 6(1.27,1.5) 7(3.81,-1.5) 8(6.35,1.5) 9(8.89,-1.5) 10(11.43,1.5)
  silkscreen extent -14.36,-2.92 12.95,1.27
FBGA90_0R8_8X13 [mm]
  oct 0.35x0.35 smd: A1(-3.2,5.6) A2(-2.4,5.6) A3(-1.6,5.6) A7(1.6,5.6) A8(2.4,5.6) A9(3.2,5.6) B1(-3.2,4.8) B2(-2.4,4.8) B3(-1.6,4.8) B7(1.6,4.8) B8(2.4,4.8) B9(3.2,4.8) C1(-3.2,4) C2(-2.4,4) C3(-1.6,4) C7(1.6,4) C8(2.4,4) C9(3.2,4) D1(-3.2,3.2) D2(-2.4,3.2) D3(-1.6,3.2) D7(1.6,3.2) D8(2.4,3.2) D9(3.2,3.2) E1(-3.2,2.4) E2(-2.4,2.4) E3(-1.6,2.4) E7(1.6,2.4) E8(2.4,2.4) E9(3.2,2.4) F1(-3.2,1.6) F2(-2.4,1.6) F3(-1.6,1.6) F7(1.6,1.6) F8(2.4,1.6) F9(3.2,1.6) G1(-3.2,0.8) G2(-2.4,0.8) G3(-1.6,0.8) G7(1.6,0.8) G8(2.4,0.8) G9(3.2,0.8) H1(-3.2,0) H2(-2.4,0) H3(-1.6,0) H7(1.6,0) H8(2.4,0) H9(3.2,0) J1(-3.2,-0.8) J2(-2.4,-0.8) J3(-1.6,-0.8) J7(1.6,-0.8) J8(2.4,-0.8) J9(3.2,-0.8) K1(-3.2,-1.6) K2(-2.4,-1.6) K3(-1.6,-1.6) K7(1.6,-1.6) K8(2.4,-1.6) K9(3.2,-1.6) L1(-3.2,-2.4) L2(-2.4,-2.4) L3(-1.6,-2.4) L7(1.6,-2.4) L8(2.4,-2.4) L9(3.2,-2.4) M1(-3.2,-3.2) M2(-2.4,-3.2) M3(-1.6,-3.2) M7(1.6,-3.2) M8(2.4,-3.2) M9(3.2,-3.2) N1(-3.2,-4) N2(-2.4,-4) N3(-1.6,-4) N7(1.6,-4) N8(2.4,-4) N9(3.2,-4) P1(-3.2,-4.8) P2(-2.4,-4.8) P3(-1.6,-4.8) P7(1.6,-4.8) P8(2.4,-4.8) P9(3.2,-4.8) R1(-3.2,-5.6) R2(-2.4,-5.6) R3(-1.6,-5.6) R7(1.6,-5.6) R8(2.4,-5.6) R9(3.2,-5.6)
  silkscreen extent -4.1,-6.6 4.1,6.6
FIX3.25NMET [mm]
  round 0.8 hole 3.25 unplated: 1(0,0)
  Keep-Out Layer circle w0.2: c0,0 r2.125
"FLIP CHIP" [mm]
  round 0.32 smd: A2(0,1) A3(0.5,1) B1(-0.5,0.5) B2(0,0.5) B3(0.5,0.5) C1(-0.5,0) C2(0,0) C3(0.5,0) D1(-0.5,-0.5) D2(0,-0.5) D3(0.5,-0.5)
  silkscreen extent -1.25,-0.9 0.9,1.4
FPU330ZH-BT1D3-CA [mm]
  rect 0.3x1.25 smd: 1(-7.25,2.575) 2(-6.75,2.575) 3(-6.25,2.575) 4(-5.75,2.575) 5(-5.25,2.575) 6(-4.75,2.575) 7(-4.25,2.575) 8(-3.75,2.575) 9(-3.25,2.575) 10(-2.75,2.575) 11(-2.25,2.575) 12(-1.75,2.575) 13(-1.25,2.575) 14(-0.75,2.575) 15(-0.25,2.575) 16(0.25,2.575) 17(0.75,2.575) 18(1.25,2.575) 19(1.75,2.575) 20(2.25,2.575) 21(2.75,2.575) 22(3.25,2.575) 23(3.75,2.575) 24(4.25,2.575) 25(4.75,2.575) 26(5.25,2.575) 27(5.75,2.575) 28(6.25,2.575) 29(6.75,2.575) 30(7.25,2.575)
  rect 2x2.5 smd: 31(8.94,0) 32(-8.94,0)
  silkscreen extent -10.34,-2.6 10.34,3.55
HCLGA_3X4X1_4LD [mm]
  rect 0.4x0.95 smd paste+0 mask+0.05: 1(0.45,-0.675) 2(0.45,0.675) 3(-0.45,0.675) 4(-0.45,-0.675)
  rect 0.35x2.3 smd paste+0 mask+0.05: 5(-1.225,0) 5(1.225,0)
  rect 1.3x0.35 smd paste+0 mask+0.05: 5(0,-1.725) 5(0,1.725)
  silkscreen extent -1.55,-2.05 1.55,2.05, body extent -1.45,-1.95 1.45,1.95, height 1.03
"HEADER 4" [mil]
  rect 70x70 hole 39.37: 1(0,0)
  round 70 hole 39.37: 2(100,0) 3(200,0) 4(300,0)
  silkscreen extent -50,-50 350,50
HSMF-A201 [mm]
  rect 1.5x1.1 smd: 1(-1.5,0.75) 2(1.5,0.75) 3(1.5,-0.75) 4(-1.5,-0.75)
  silkscreen extent -1.7,-1.6 1.7,1.6
"IMPEDANCE BOARD 8" [mm]
JP2_SMD [mil]
  round 10 smd paste-393.7: 1(-19.69,0) 2(23.62,0)
  Top region: -9.84,-19.69 49.21,-19.69 49.21,19.69 -9.84,19.69 9.84,0
  Top region: -19.69,19.69 -49.21,19.69 -49.21,-19.69 -19.69,-19.69 0,0
"LCD_Kunjian_ HT043C_40P_P080_FLEX_FOLDED" [mm]
  rect 0.5x2 smd mask+0.05: 1(-15.6,-2) 2(-14.8,-2) 3(-14,-2) 4(-13.2,-2) 5(-12.4,-2) 6(-11.6,-2) 7(-10.8,-2) 8(-10,-2) 9(-9.2,-2) 10(-8.4,-2) 11(-7.6,-2) 12(-6.8,-2) 13(-6,-2) 14(-5.2,-2) 15(-4.4,-2) 16(-3.6,-2) 17(-2.8,-2) 18(-2,-2) 19(-1.2,-2) 20(-0.4,-2) 21(0.4,-2) 22(1.2,-2) 23(2,-2) 24(2.8,-2) 25(3.6,-2) 26(4.4,-2) 27(5.2,-2) 28(6,-2) 29(6.8,-2) 30(7.6,-2) 31(8.4,-2) 32(9.2,-2) 33(10,-2) 34(10.8,-2) 35(11.6,-2) 36(12.4,-2) 37(13.2,-2) 38(14,-2) 39(14.8,-2) 40(15.6,-2)
  round 0 hole 1 unplated mask+0.05: NPTH1(-17.6,-2) NPTH2(17.6,-2)
  silkscreen extent -52.75,-36.93 52.75,33.6, body extent -52.75,-36.93 52.75,33.6, height 7.6
NZ2520SH_4P [mm]
  rect 1x1 smd mask+0.05: 1(-0.825,-0.625) 2(0.825,-0.625) 3(0.825,0.625) 4(-0.825,0.625)
  silkscreen extent -1.43,-1.22 1.2,1.05, body extent -1.3,-1.05 1.3,1.05, height 0.91
PJ3028B [mm]
  round 0.8 hole 2 unplated: 1(-3.5,0) 8(3.5,0)
  rect 1.5x2.5 smd: 2(-7.25,-3.45) 7(-5.65,3.45)
  rect 2x2.5 smd: 3(-4.5,-3.45) 4(-2.7,3.45) 6(4.7,-3.45)
  rect 2.5x2 smd: 5(8.75,0.75)
  silkscreen extent -9.5,-3 7.5,3
PJS008-2003-1 [mm]
  rect 1.6x0.8 smd paste+0 mask+0.05: 1(-15.6,-2.525) 2(-15.6,-1.425) 3(-15.6,-0.325) 4(-15.6,0.775) 5(-15.6,1.875) 6(-15.6,2.975) 7(-15.6,4.075) 8(-15.6,5.175) 9(-15.6,6.325)
  rect 1.4x1.95 smd paste+0 mask+0.05: 10(-5.4,7.225)
  rect 3.5x1.5 smd paste+0 mask+0.05: 11(-2.45,7.45)
  rect 3.5x1.4 smd paste+0 mask+0.05: 12(-2.45,-7.5)
  rect 3.5x1.6 smd paste+0 mask+0.05: 13(-13.45,-7.4)
  rect 3.1x1.2 smd paste+0 mask+0.05: 14(-13.95,7.6)
  round 0 hole 0.65 unplated mask+0.05: NPTH1(-9.8,-4)
  round 0 hole 0.7 unplated mask+0.05: NPTH2(-9.8,3.55)
  silkscreen extent -15.32,-7.25 5.65,7.25, body extent -15.04,-7.18 -0.84,7.42, height 2
QFN8_0R65_3X3_ST [mm]
  rect 0.4x0.7 smd: 1(-0.975,-1.425) 2(-0.325,-1.425) 3(0.325,-1.425) 4(0.975,-1.425) 5(0.975,1.425) 6(0.325,1.425) 7(-0.325,1.425) 8(-0.975,1.425)
  rect 2.64x1.9 smd: 9(0,0)
  Top region: -1.275,-0.9 -1.275,-0.35 -1.575,-0.35 -1.575,-0.2 -1.275,-0.2 -1.275,0.2 -1.575,0.2 -1.575,0.35 -1.275,0.35 -1.275,0.9 1.275,0.9 1.275,0.35 1.575,0.35 1.575,0.2 1.275,0.2 1.275,-0.2 1.575,-0.2 1.575,-0.35 1.275,-0.35 1.275,-0.9
  silkscreen extent -1.5,-2 1.5,2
